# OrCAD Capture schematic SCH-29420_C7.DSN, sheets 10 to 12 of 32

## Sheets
10 P07_POWER SUPPLY: size A2
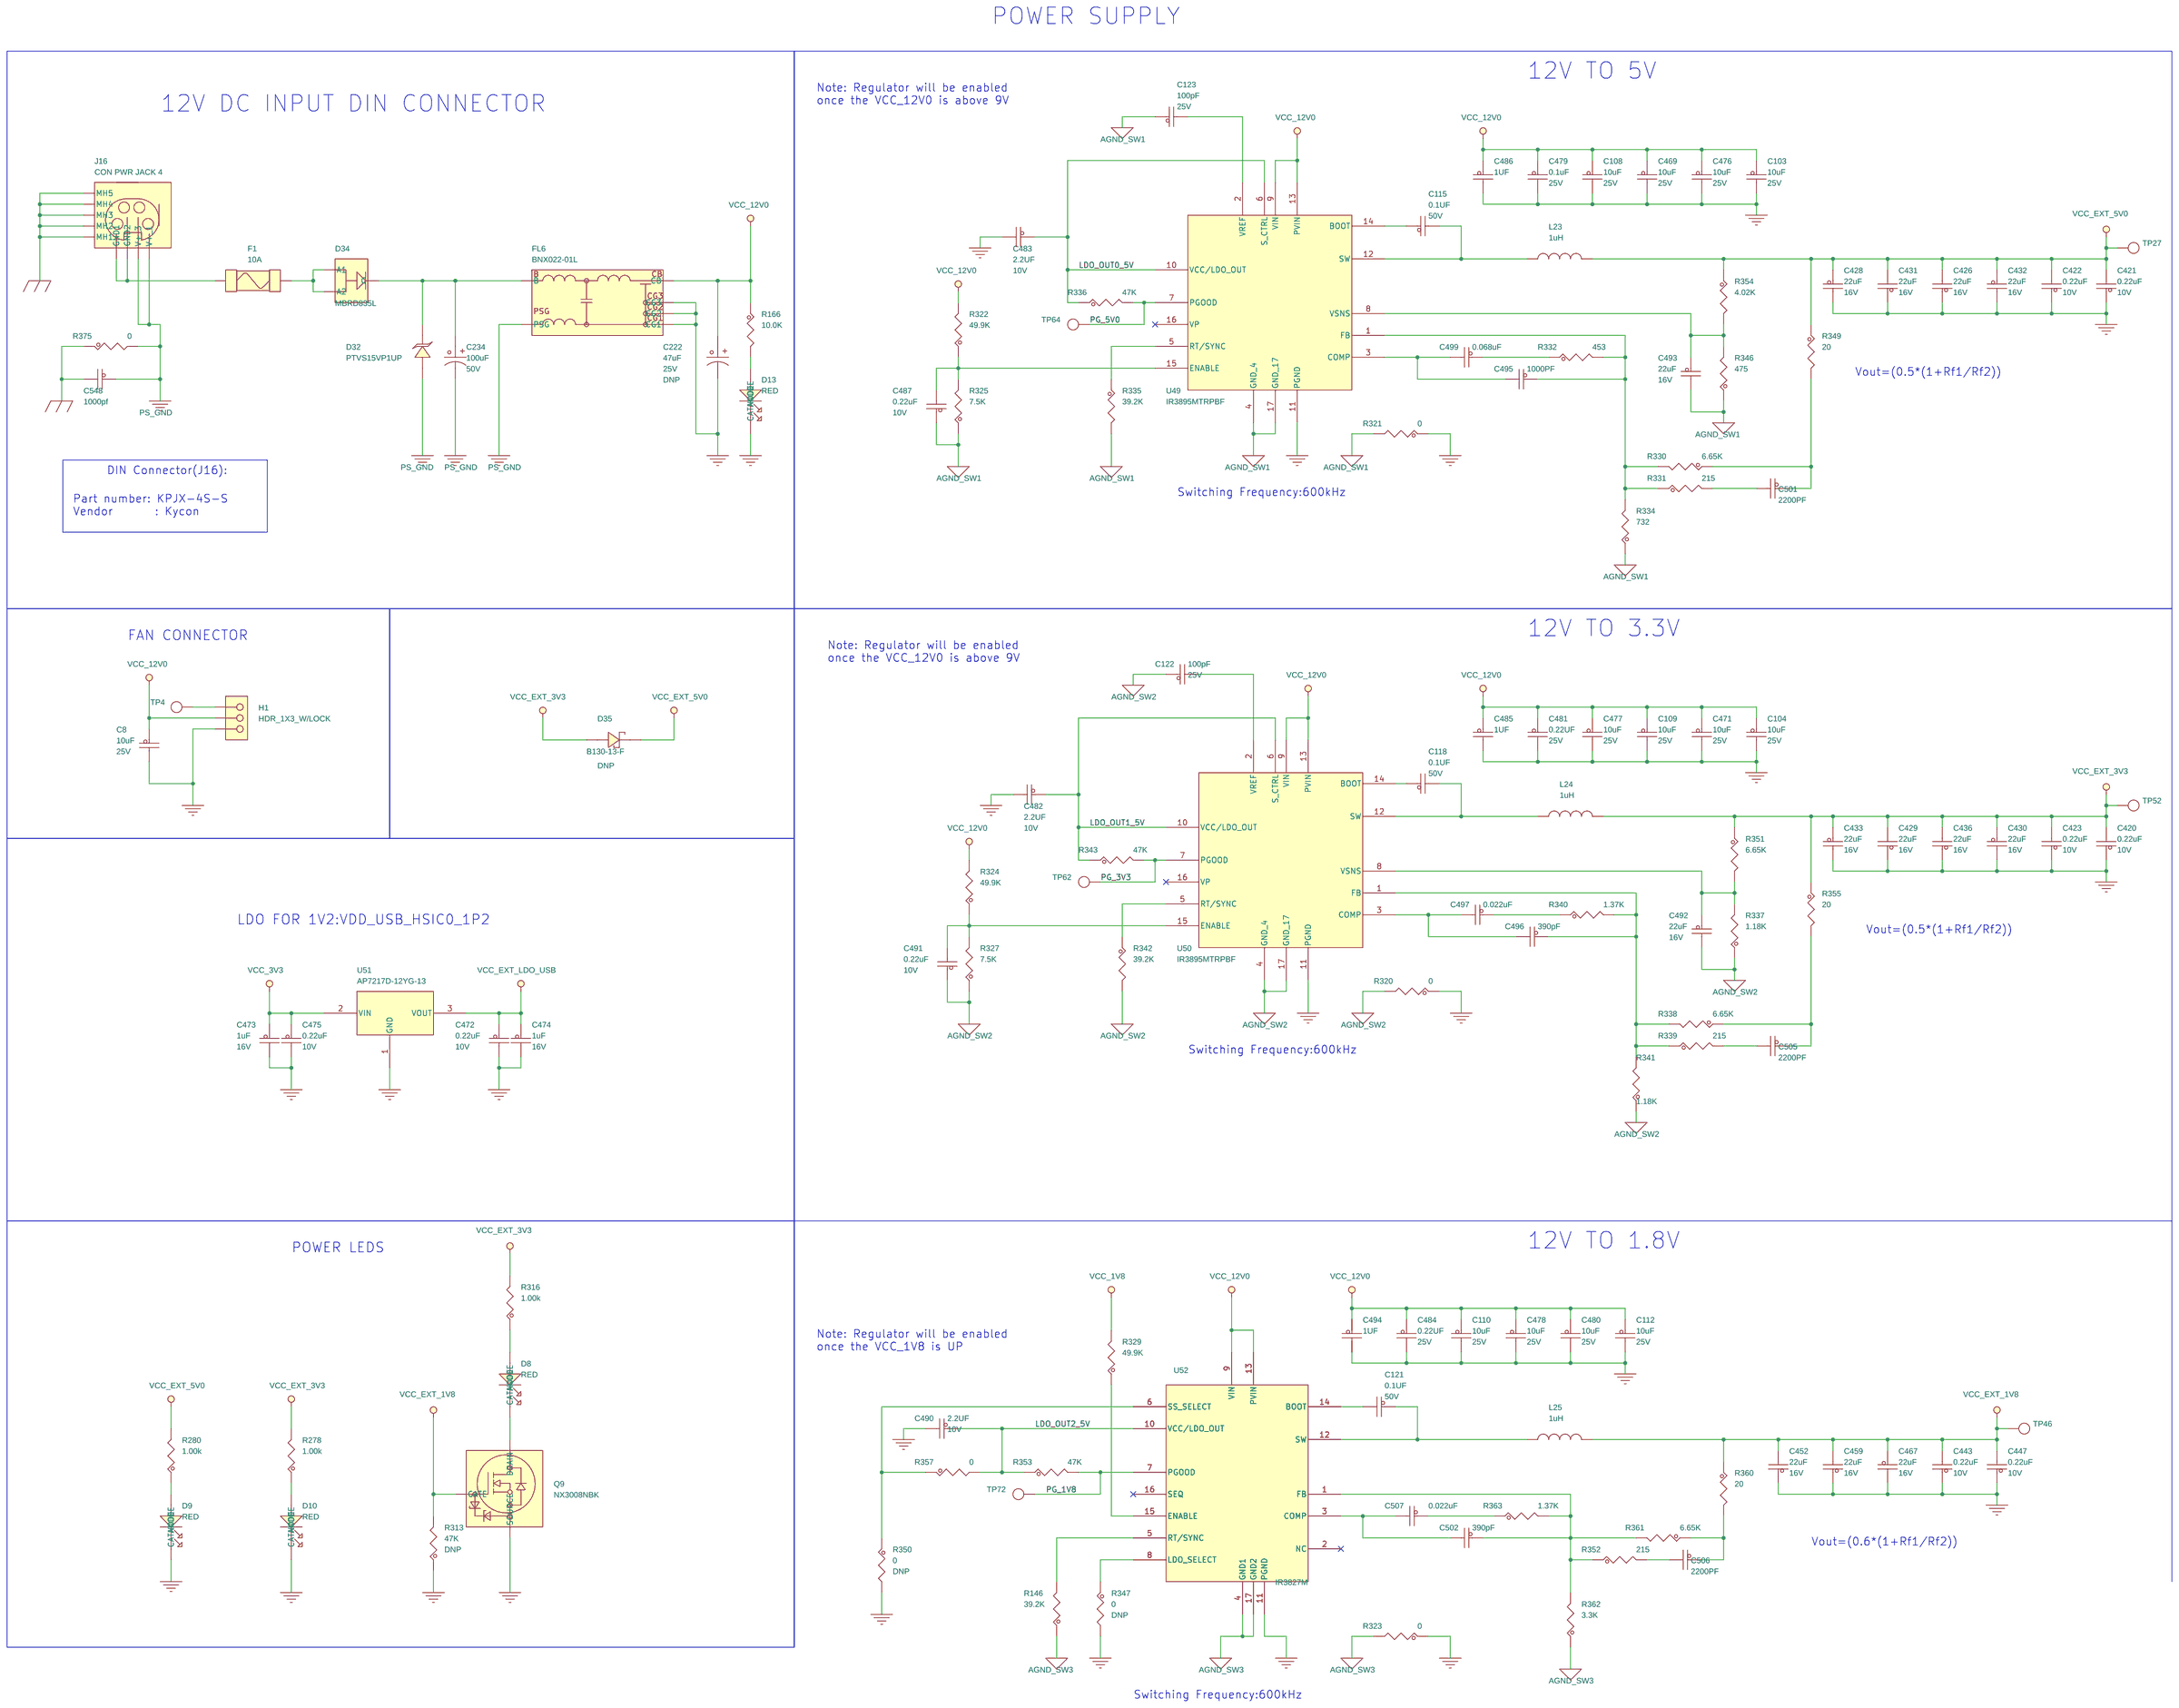
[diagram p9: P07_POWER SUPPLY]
11 P08_PMIC_1: size A2
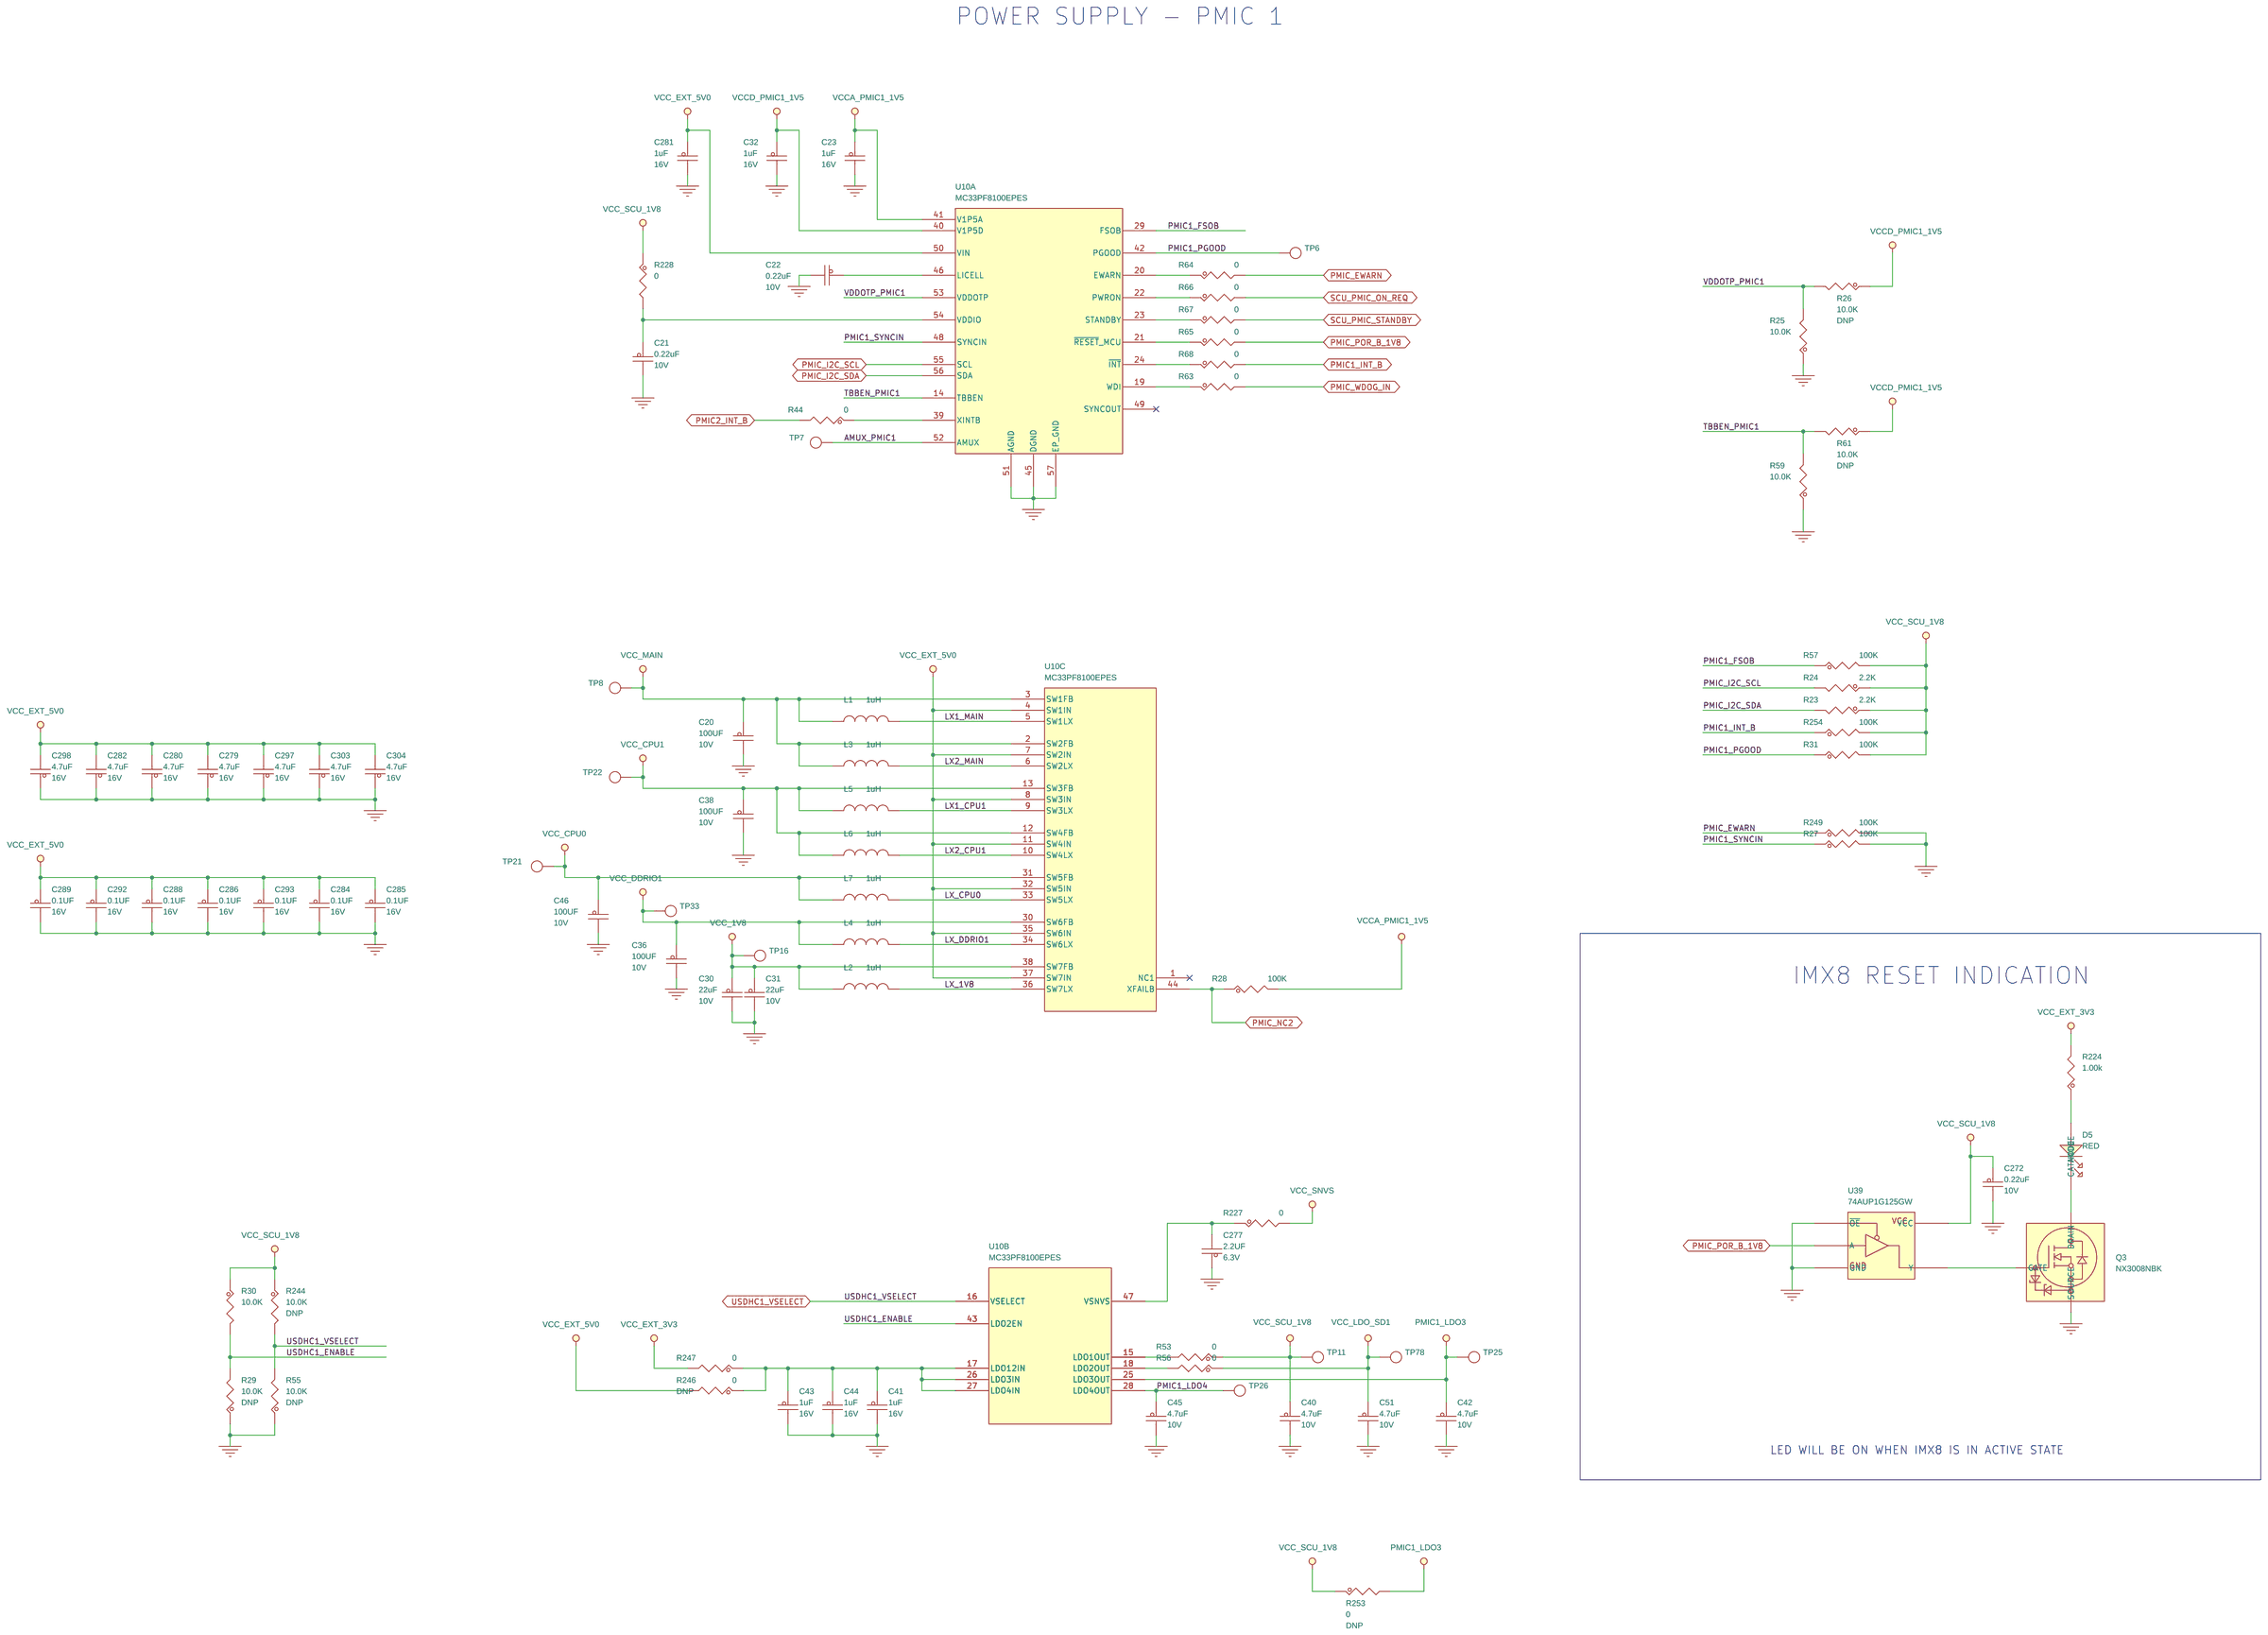
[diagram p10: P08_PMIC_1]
12 P10_MX8QM_POWER: size A2
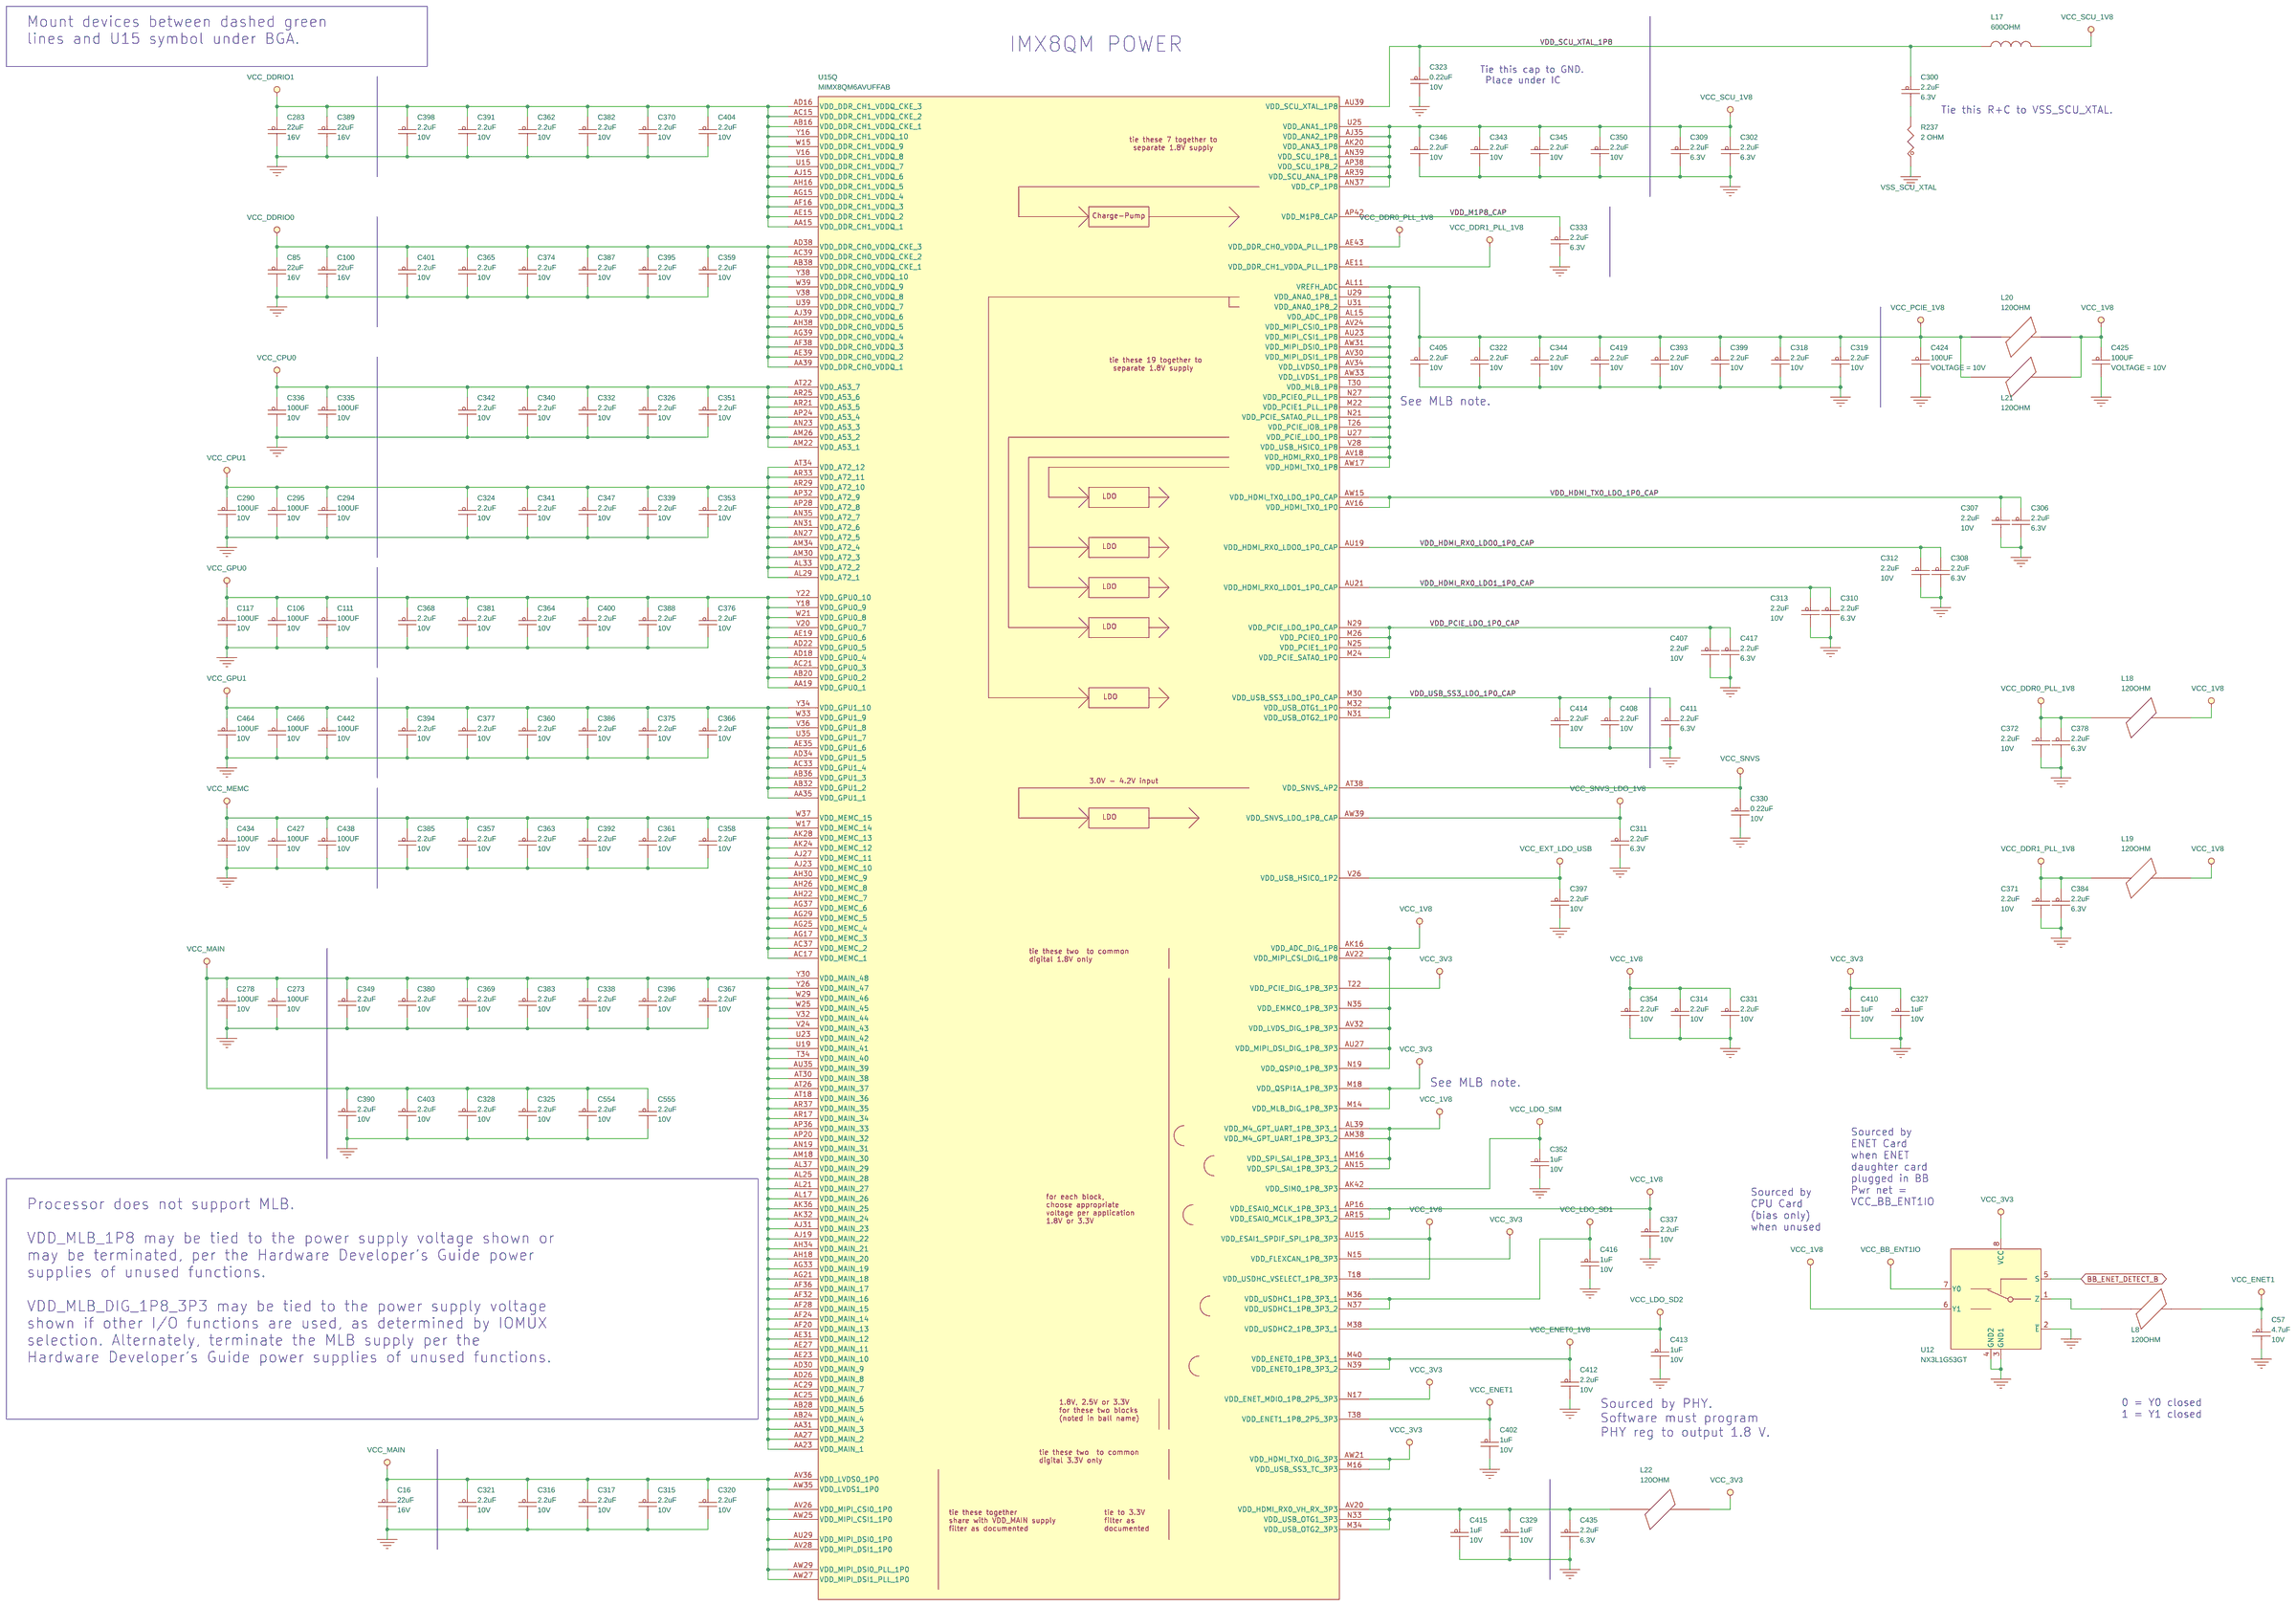
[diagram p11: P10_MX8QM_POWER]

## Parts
sheet P07_POWER SUPPLY
C8  10uF  [CC0603_OV]
C103  10uF  [CC0603_OV]
C104  10uF  [CC0603_OV]
C108  10uF  [CC0603_OV]
C109  10uF  [CC0603_OV]
C110  10uF  [CC0603_OV]
C112  10uF  [CC0603_OV]
C115  0.1UF  [CC0402_25]
C118  0.1UF  [CC0402_25]
C121  0.1UF  [CC0402_25]
C122  100pF  [CC0402_25]
C123  100pF  [CC0402_25]
C222  47uF  [cce6p8x6p8]
C234  100uF  [cce6p8x6p8]
C420  0.22uF  [CC0402_25]
C421  0.22uF  [CC0402_25]
C422  0.22uF  [CC0402_25]
C423  0.22uF  [CC0402_25]
C426  22uF  [CC0805_OV]
C428  22uF  [CC0805_OV]
C429  22uF  [CC0805_OV]
C430  22uF  [CC0805_OV]
C431  22uF  [CC0805_OV]
C432  22uF  [CC0805_OV]
C433  22uF  [CC0805_OV]
C436  22uF  [CC0805_OV]
C443  0.22uF  [CC0402_25]
C447  0.22uF  [CC0402_25]
C452  22uF  [CC0805_OV]
C459  22uF  [CC0805_OV]
C467  22uF  [CC0805_OV]
C469  10uF  [CC0603_OV]
C471  10uF  [CC0603_OV]
C472  0.22uF  [CC0402_25]
C473  1uF  [CC0402_25]
C474  1uF  [CC0402_25]
C475  0.22uF  [CC0402_25]
C476  10uF  [CC0603_OV]
C477  10uF  [CC0603_OV]
C478  10uF  [CC0603_OV]
C479  0.1uF  [CC0402_25]
C480  10uF  [CC0603_OV]
C481  0.22UF  [CC0805_OV]
C482  2.2UF  [CC0402_25]
C483  2.2UF  [CC0402_25]
C484  0.22UF  [CC0805_OV]
C485  1UF  [CC0603_OV]
C486  1UF  [CC0603_OV]
C487  0.22uF  [CC0402_25]
C490  2.2UF  [CC0402_25]
C491  0.22uF  [CC0402_25]
C492  22uF  [CC0805_OV]
C493  22uF  [CC0805_OV]
C494  1UF  [CC0603_OV]
C495  1000PF  [CC0402_25]
C496  390pF  [CC0402_25]
C497  0.022uF  [CC0402_25]
C499  0.068uF  [CC0603_OV]
C501  2200PF  [CC0402_25]
C502  390pF  [CC0402_25]
C505  2200PF  [CC0402_25]
C506  2200PF  [CC0402_25]
C507  0.022uF  [CC0402_25]
C548  1000pf  [CC1210]
D8  RED  [LED_0603]
D9  RED  [LED_0603]
D10  RED  [LED_0603]
D13  RED  [LED_0603]
D32  PTVS15VP1UP  [sod-128]
D34  MBRD835L  [DPAK]
D35  B130-13-F  [sma2_4_4p6x2p9]
F1  10A  [FUSE_BLOCK_154]
FL6  BNX022-01L  [filter6_12p3x9p3]
H1  HDR_1X3_W/LOCK  [hdr1x3_100_294x250_th]
J16  CON PWR JACK 4  [jack_pwr_ra_4p]
L23  1uH  [ind2_10p7x10p7]
L24  1uH  [ind2_10p7x10p7]
L25  1uH  [ind2_4p3sq_xfl4020]
Q9  NX3008NBK  [SOT23_A]
R146  39.2K  [RC0402_25]
R166  10.0K  [RC0402_25]
R278  1.00k  [RC0402_25]
R280  1.00k  [RC0402_25]
R313  47K  [RC0402_25]
R316  1.00k  [RC0402_25]
R320  0  [RC0402_25]
R321  0  [RC0402_25]
R322  49.9K  [RC0402_25]
R323  0  [RC0402_25]
R324  49.9K  [RC0402_25]
R325  7.5K  [RC0402_25]
R327  7.5K  [RC0402_25]
R329  49.9K  [RC0402_25]
R330  6.65K  [RC0402_25]
R331  215  [RC0402_25]
R332  453  [RC0402_25]
R334  732  [RC0402_25]
R335  39.2K  [RC0402_25]
R336  47K  [RC0402_25]
R337  1.18K  [RC0402_25]
R338  6.65K  [RC0402_25]
R339  215  [RC0402_25]
R340  1.37K  [RC0402_25]
R341  1.18K  [RC0402_25]
R342  39.2K  [RC0402_25]
R343  47K  [RC0402_25]
R346  475  [RC0402_25]
R347  0  [RC0402_25]
R349  20  [RC0402_25]
R350  0  [RC0402_25]
R351  6.65K  [RC0402_25]
R352  215  [RC0402_25]
R353  47K  [RC0402_25]
R354  4.02K  [RC0402_25]
R355  20  [RC0402_25]
R357  0  [RC0402_25]
R360  20  [RC0402_25]
R361  6.65K  [RC0402_25]
R362  3.3K  [RC0402_25]
R363  1.37K  [RC0402_25]
R375  0  [RC0402_25]
TP4  TPAD_050  [TPAD_050]
TP27  TPAD_050  [TPAD_050]
TP46  TPAD_050  [TPAD_050]
TP52  TPAD_050  [TPAD_050]
TP62  TPAD_050  [TPAD_050]
TP64  TPAD_050  [TPAD_050]
TP72  TPAD_050  [TPAD_050]
U49  IR3895MTRPBF  [qfn17_0p65_5x6]
U50  IR3895MTRPBF  [qfn17_0p65_5x6]
U51  AP7217D-12YG-13  [sot89_123]
U52  IR3827M  [QFN17_0P5_4X5]
sheet P08_PMIC_1
C20  100UF  [CC1210]
C21  0.22uF  [CC0402_25]
C22  0.22uF  [CC0402_25]
C23  1uF  [CC0402_25]
C30  22uF  [CC0603_OV]
C31  22uF  [CC0603_OV]
C32  1uF  [CC0402_25]
C36  100UF  [CC1210]
C38  100UF  [CC1210]
C40  4.7uF  [CC0402_25]
C41  1uF  [CC0402_25]
C42  4.7uF  [CC0402_25]
C43  1uF  [CC0402_25]
C44  1uF  [CC0402_25]
C45  4.7uF  [CC0402_25]
C46  100UF  [CC1210]
C51  4.7uF  [CC0402_25]
C272  0.22uF  [CC0402_25]
C277  2.2UF  [CC0402_25]
C279  4.7uF  [CC0603_OV]
C280  4.7uF  [CC0603_OV]
C281  1uF  [CC0402_25]
C282  4.7uF  [CC0603_OV]
C284  0.1UF  [CC0402_25]
C285  0.1UF  [CC0402_25]
C286  0.1UF  [CC0402_25]
C288  0.1UF  [CC0402_25]
C289  0.1UF  [CC0402_25]
C292  0.1UF  [CC0402_25]
C293  0.1UF  [CC0402_25]
C297  4.7uF  [CC0603_OV]
C298  4.7uF  [CC0603_OV]
C303  4.7uF  [CC0603_OV]
C304  4.7uF  [CC0603_OV]
D5  RED  [LED_0603]
L1  1uH  [ind2520]
L2  1uH  [ind2520]
L3  1uH  [ind2520]
L4  1uH  [ind2520]
L5  1uH  [ind2520]
L6  1uH  [ind2520]
L7  1uH  [ind2520]
Q3  NX3008NBK  [SOT23_A]
R23  2.2K  [RC0402_25]
R24  2.2K  [RC0402_25]
R25  10.0K  [RC0402_25]
R26  10.0K  [RC0402_25]
R27  100K  [RC0402_25]
R28  100K  [RC0402_25]
R29  10.0K  [RC0402_25]
R30  10.0K  [RC0402_25]
R31  100K  [RC0402_25]
R44  0  [RC0402_25]
R53  0  [RC0402_25]
R55  10.0K  [RC0402_25]
R56  0  [RC0402_25]
R57  100K  [RC0402_25]
R59  10.0K  [RC0402_25]
R61  10.0K  [RC0402_25]
R63  0  [RC0402_25]
R64  0  [RC0402_25]
R65  0  [RC0402_25]
R66  0  [RC0402_25]
R67  0  [RC0402_25]
R68  0  [RC0402_25]
R224  1.00k  [RC0402_25]
R227  0  [RC0402_25]
R228  0  [RC0402_25]
R244  10.0K  [RC0402_25]
R246  0  [RC0402_25]
R247  0  [RC0402_25]
R249  100K  [RC0402_25]
R253  0  [RC0402_25]
R254  100K  [RC0402_25]
TP6  TPAD_050  [TPAD_050]
TP7  TPAD_050  [TPAD_050]
TP8  TPAD_050  [TPAD_050]
TP11  TPAD_050  [TPAD_050]
TP16  TPAD_050  [TPAD_050]
TP21  TPAD_050  [TPAD_050]
TP22  TPAD_050  [TPAD_050]
TP25  TPAD_050  [TPAD_050]
TP26  TPAD_050  [TPAD_050]
TP33  TPAD_050  [TPAD_050]
TP78  TPAD_050  [TPAD_050]
U10  MC33PF8100EPES  [qfn56_0p5_8x8_ep217x199]  (sections A,B,C)
U39  74AUP1G125GW  [SC70-5]
sheet P10_MX8QM_POWER
C16  22uF  [CC1210]
C57  4.7uF  [CC0603_OV]
C85  22uF  [CC1210]
C100  22uF  [CC1210]
C106  100UF  [CC1210]
C111  100UF  [CC1210]
C117  100UF  [CC1210]
C273  100UF  [CC1210]
C278  100UF  [CC1210]
C283  22uF  [CC1210]
C290  100UF  [CC1210]
C294  100UF  [CC1210]
C295  100UF  [CC1210]
C300  2.2uF  [CC0603_OV]
C302  2.2uF  [CC0603_OV]
C306  2.2uF  [CC0603_OV]
C307  2.2uF  [CC0402_25]
C308  2.2uF  [CC0603_OV]
C309  2.2uF  [CC0603_OV]
C310  2.2uF  [CC0603_OV]
C311  2.2uF  [CC0603_OV]
C312  2.2uF  [CC0402_25]
C313  2.2uF  [CC0402_25]
C314  2.2uF  [CC0402_25]
C315  2.2uF  [CC0402_25]
C316  2.2uF  [CC0402_25]
C317  2.2uF  [CC0402_25]
C318  2.2uF  [CC0402_25]
C319  2.2uF  [CC0402_25]
C320  2.2uF  [CC0402_25]
C321  2.2uF  [CC0402_25]
C322  2.2uF  [CC0402_25]
C323  0.22uF  [CC0402_25]
C324  2.2uF  [0402_CC]
C325  2.2uF  [0402_CC]
C326  2.2uF  [CC0402_25]
C327  1uF  [0402_CC]
C328  2.2uF  [0402_CC]
C329  1uF  [0402_CC]
C330  0.22uF  [CC0402_25]
C331  2.2uF  [0402_CC]
C332  2.2uF  [0402_CC]
C333  2.2uF  [CC0603_OV]
C335  100UF  [CC1210]
C336  100UF  [CC1210]
C337  2.2uF  [CC0402_25]
C338  2.2uF  [0402_CC]
C339  2.2uF  [0402_CC]
C340  2.2uF  [0402_CC]
C341  2.2uF  [0402_CC]
C342  2.2uF  [0402_CC]
C343  2.2uF  [0402_CC]
C344  2.2uF  [CC0402_25]
C345  2.2uF  [0402_CC]
C346  2.2uF  [0402_CC]
C347  2.2uF  [0402_CC]
C349  2.2uF  [0402_CC]
C350  2.2uF  [0402_CC]
C351  2.2uF  [0402_CC]
C352  1uF  [0402_CC]
C353  2.2uF  [0402_CC]
C354  2.2uF  [CC0402_25]
C357  2.2uF  [0402_CC]
C358  2.2uF  [0402_CC]
C359  2.2uF  [CC0402_25]
C360  2.2uF  [0402_CC]
C361  2.2uF  [0402_CC]
C362  2.2uF  [CC0402_25]
C363  2.2uF  [0402_CC]
C364  2.2uF  [0402_CC]
C365  2.2uF  [CC0402_25]
C366  2.2uF  [0402_CC]
C367  2.2uF  [0402_CC]
C368  2.2uF  [0402_CC]
C369  2.2uF  [0402_CC]
C370  2.2uF  [CC0402_25]
C371  2.2uF  [CC0402_25]
C372  2.2uF  [CC0402_25]
C374  2.2uF  [CC0402_25]
C375  2.2uF  [0402_CC]
C376  2.2uF  [0402_CC]
C377  2.2uF  [0402_CC]
C378  2.2uF  [CC0603_OV]
C380  2.2uF  [0402_CC]
C381  2.2uF  [0402_CC]
C382  2.2uF  [CC0402_25]
C383  2.2uF  [0402_CC]
C384  2.2uF  [CC0603_OV]
C385  2.2uF  [0402_CC]
C386  2.2uF  [0402_CC]
C387  2.2uF  [CC0402_25]
C388  2.2uF  [0402_CC]
C389  22uF  [CC1210]
C390  2.2uF  [0402_CC]
C391  2.2uF  [CC0402_25]
C392  2.2uF  [0402_CC]
C393  2.2uF  [0402_CC]
C394  2.2uF  [0402_CC]
C395  2.2uF  [CC0402_25]
C396  2.2uF  [0402_CC]
C397  2.2uF  [0402_CC]
C398  2.2uF  [CC0402_25]
C399  2.2uF  [0402_CC]
C400  2.2uF  [0402_CC]
C401  2.2uF  [CC0402_25]
C402  1uF  [0402_CC]
C403  2.2uF  [0402_CC]
C404  2.2uF  [CC0402_25]
C405  2.2uF  [0402_CC]
C407  2.2uF  [0402_CC]
C408  2.2uF  [0402_CC]
C410  1uF  [CC0402_25]
C411  2.2uF  [CC0603_OV]
C412  2.2uF  [CC0402_25]
C413  1uF  [CC0402_25]
C414  2.2uF  [CC0402_25]
C415  1uF  [CC0402_25]
C416  1uF  [CC0402_25]
C417  2.2uF  [CC0603_OV]
C419  2.2uF  [CC0402_25]
C424  100UF  [CC1210]
C425  100UF  [CC1210]
C427  100UF  [CC1210]
C434  100UF  [CC1210]
C435  2.2uF  [CC0603_OV]
C438  100UF  [CC1210]
C442  100UF  [CC1210]
C464  100UF  [CC1210]
C466  100UF  [CC1210]
C554  2.2uF  [0402_CC]
C555  2.2uF  [0402_CC]
L8  120OHM  [IND_0603]
L17  600OHM  [ind_1p8x1mm_sm]
L18  120OHM  [IND_0603]
L19  120OHM  [IND_0603]
L20  120OHM  [IND_0603]
L21  120OHM  [IND_0603]
L22  120OHM  [IND_0603]
R237  2 OHM  [RC0402_25]
U12  NX3L1G53GT  [xson_8p]
sheet P20_USB3.x_TYPE_C
U15  MIMX8QM6AVUFFAB  [imx8_bga_1313]  (sections A,B,C,D,E,F,G,H,I,J,K,L,M,N,O,P,Q,R,S,T,U)

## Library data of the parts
C8 C103 C104 C108-C110 C112 C469 C471 C476-C478 C480 = CAP_NP: CAP CER 10uF 25V 20% X5R 0603; AGILE_PN: 150-79272; CAD_APPROVED: Yes; EN: 102-1-01982; FPLIST: CC0603_OV,CC0603,0603_CC; HEIGHT: 1MM; MFG_NAME01: Murata; MFG_PN01: GRM188R61E106MA73D; ROHS: Yes; TOL: 20%; Tolerance: 20%; VOLTAGE: 25V
C115 C118 C121 = CAP_NP: CAP CER 0.1UF 50V 10% X5R 0402; AGILE_PN: 150-79249; CAD_APPROVED: Yes; EN: 102-1-01811; FPLIST: CC0402_25,CC0402_HD,0402_CC; HEIGHT: 0.55MM; MFG_NAME01: MURATA; MFG_PN01: GRM155R61H104KE19; ROHS: Yes; TOL: 10%; Tolerance: 10%; VOLTAGE: 50V
C122 C123 = CAP_NP: CAP CER 100pF 25V 10% X7R 0402; AGILE_PN: 150-30222; CAD_APPROVED: Yes; EN: 102-1-00028; FPLIST: CC0402_25,CC0402_HD,0402_CC; HEIGHT: 0.55MM; MFG_NAME01: YAGEO AMERICA; MFG_PN01: CC0402KRX7R8BB101; ROHS: Yes; TOL: 10%; Tolerance: 10%; VOLTAGE: 25V
C222 = CAP_POL: CAP ALEL 47uF 35V 20% -- AEC-Q200 SMT; AGILE_PN: 150-79508; ASSY_OPT: DNP; CAD_APPROVED: Yes; EN: 102-3-00024; HEIGHT: 5.5 MM; MFG_NAME01: Panasonic; MFG_PN01: EEE1VA470WAP; ROHS: Yes; VOLTAGE: 25V
C234 = CAP_POL: CAP ALEL 100uF 50V 20% -- AEC-Q200 SMT; AGILE_PN: 150-80098; CAD_APPROVED: Yes; EN: 102-3-00161; HEIGHT: 8 MM; MFG_NAME01: PANASONIC; MFG_PN01: EEE-FTH101XAP; ROHS: Yes; TOL: 20%; Temp_Range: -55°C to +105°C; Tolerance: 20%; VOLTAGE: 50V
C21 C22 C272 C323 C330 C420-C423 C443 C447 C472 C475 C487 C491 = CAP_NP: CAP CER 0.22uF 10V 10% X7R AEC-Q200 0402; AGILE_PN: 150-79031; CAD_APPROVED: Yes; EN: 102-1-01816; FPLIST: CC0402_25,CC0402_HD,0402_CC; HEIGHT: 0.55MM; MFG_NAME01: TDK; MFG_PN01: CGA2B1X7R1A224K050BC; ROHS: Yes; TOL: 10%; Tolerance: 10%; VOLTAGE: 10V
C426 C428-C433 C436 C452 C459 C467 C492 C493 = CAP_NP: CAP CER 22UF 16V 10% X5R 0805; AGILE_PN: 150-78843; CAD_APPROVED: Yes; EN: 102-1-01914; FPLIST: CC0805_OV,CC0805,0805_CC; HEIGHT: 1.45MM; MFG_NAME01: TDK; MFG_PN01: C2012X5R1C226K; ROHS: Yes; TOL: 10%; Tolerance: 10%; VOLTAGE: 16V
C23 C32 C41 C43 C44 C281 C473 C474 = CAP_NP: CAP CER 1uF 16V 10% X5R 0402; AGILE_PN: 150-79794; CAD_APPROVED: Yes; EN: 102-1-01641; FPLIST: CC0402_25,CC0402_HD,0402_CC; HEIGHT: 0.55MM; MFG_NAME01: NIC COMPONENTS CORP; MFG_PN01: NMC0402X5R105K16TRPF; ROHS: Yes; TOL: +/-10%; Tolerance: +/-10%; VOLTAGE: 16V
C479 = CAP_NP: CAP CER 0.1UF 25V 10% X5R 0402; AGILE_PN: 150-78633; CAD_APPROVED: Yes; EN: 102-1-01693; FPLIST: CC0402_25,CC0402_HD,0402_CC; HEIGHT: 0.55MM; MFG_NAME01: YAGEO AMERICA; MFG_PN01: CC0402KRX5R8BB104; ROHS: Yes; TOL: 10%; Tolerance: 10%; VOLTAGE: 25V
C481 C484 = CAP_NP: CAP CER 0.22UF 25V 10% X7R 0805; AGILE_PN: 150-75497; CAD_APPROVED: Yes; EN: 102-1-00372; FPLIST: CC0805_OV,CC0805,0805_CC; HEIGHT: 1.4732MM; MFG_NAME01: AVX; MFG_PN01: 08053C224KAT2A; ROHS: Yes; TOL: 10%; Tolerance: 10%; VOLTAGE: 25V
C482 C483 C490 = CAP_NP: CAP CER 2.2UF 10V 10% X5R 0402; AGILE_PN: 150-79475; CAD_APPROVED: Yes; EN: 102-1-00208; FPLIST: CC0402_25,CC0402_HD,0402_CC; HEIGHT: 0.56MM; MFG_NAME01: AVX; MFG_PN01: 0402ZD225KAT2A; ROHS: Yes; TOL: 10%; Tolerance: 10%; VOLTAGE: 10V
C485 C486 C494 = CAP_NP: CAP CER 1.0UF 25V 10% X5R 0603; AGILE_PN: 150-78563; CAD_APPROVED: Yes; EN: 102-1-01668; FPLIST: CC0603_OV,CC0603,0603_CC; HEIGHT: 0.95MM; MFG_NAME01: AVX; MFG_PN01: 06033D105KAT2A; ROHS: Yes
C495 = CAP_NP: CAP CER 1000PF 50V 10% X7R 0402; AGILE_PN: 150-75271; CAD_APPROVED: Yes; EN: 102-1-00011; FPLIST: CC0402_25,CC0402_HD,0402_CC; HEIGHT: 0.635 MM; MFG_NAME01: AVX; MFG_PN01: 04025C102KAT2A; ROHS: Yes; TOL: +10%; Tolerance: +10%; VOLTAGE: 50VDC
C496 C502 = CAP_NP: CAP CER 390PF 10V 10% X7R 0402; AGILE_PN: 150-80103; CAD_APPROVED: Yes; EN: 102-1-00020; FPLIST: CC0402_25,CC0402_HD,0402_CC; HEIGHT: 0.56MM; MFG_NAME01: AVX; MFG_PN01: 0402ZC391KAT2A; ROHS: Yes; TOL: 10%; Temp_Range: -55°C ~ 125°C; Tolerance: 10%; VOLTAGE: 10V
C497 C507 = CAP_NP: CAP CER 0.022uF 10V 10% X7R 0402; AGILE_PN: 150-80102; CAD_APPROVED: Yes; EN: 102-1-00005; FPLIST: CC0402_25,CC0402_HD,0402_CC; HEIGHT: 0.56MM; MFG_NAME01: AVX; MFG_PN01: 0402ZC223KAT2A; ROHS: Yes; TOL: 10%; Temp_Range: -55°C ~ 125°C; Tolerance: 10%; VOLTAGE: 10V
C499 = CAP_NP: CAP CER 0.068uF 10V 10% X7R 0603; AGILE_PN: 150-80105; CAD_APPROVED: Yes; EN: 102-1-00089; FPLIST: CC0603_OV,CC0603,0603_CC; HEIGHT: 0.9MM; MFG_NAME01: AVX; MFG_PN01: 0603ZC683KAT2A; ROHS: Yes; TOL: 10%; Temp_Range: -55°C ~ 125°C; Tolerance: 10%; VOLTAGE: 10V
C501 C505 C506 = CAP_NP: CAP CER 2200PF 50V 10%  X7R 0402; AGILE_PN: 150-75600; CAD_APPROVED: Yes; EN: 102-1-00062; FPLIST: CC0402_25,CC0402_HD,0402_CC; HEIGHT: 0.55MM; MFG_NAME01: AVX; MFG_PN01: 04025C222KAT2A; ROHS: Yes; TOL: 10%; Tolerance: 10%; VOLTAGE: 50V
C548 = CAP_NP: CAP CER 1000PF 2KV 10% X7R 1210; AGILE_PN: 150-75027; CAD_APPROVED: Yes; EN: 102-1-01612; FPLIST: CC1210,1210_CC; HEIGHT: 1.7MM; MFG_NAME01: AVX; MFG_PN01: 1210GC102KAT1A; ROHS: Yes; TOL: 10%; Tolerance: 10%; VOLTAGE: 2KV
D5 D8-D10 D13 = LED: LED RED SGL 20MA 0603; AGILE_PN: 370-76632; CAD_APPROVED: Yes; EN: 106-4-00247; HEIGHT: 0.45MM; MFG_NAME01: LITE ON; MFG_PN01: LTST-C193KRKT-5A; ROHS: Yes
D32 = DIODE_TVS: DIODE TVS 15V 600W AEC-Q101 SOD-128; AGILE_PN: 480-79835; CAD_APPROVED: Yes; EN: 305-1-00318; HEIGHT: 1.1MM; MFG_NAME01: NEXPERIA; MFG_PN01: PTVS15VP1UP,115; ROHS: Yes
D34 = MBRD835LG: DIODE PWR RECT 8A 35V DPAK; AGILE_PN: 480-30009; CAD_APPROVED: Yes; EN: 106-2-00106; HEIGHT: 2.38mm; MFG_NAME01: ON SEMICONDUCTOR; ROHS: Yes
D35 = DIODE_SCHTKY: DIODE SCH RECT 1A 30V SMA; AGILE_PN: 480-79846; ASSY_OPT: DNP; CAD_APPROVED: Yes; EN: 106-2-00016; HEIGHT: 2.5MM; MFG_NAME01: Diodes Inc; ROHS: Yes; Temp_Range: -65C to 150C
F1 = FUSE: FUSE FAST 10A 125V SMT; AGILE_PN: 510-75758; CAD_APPROVED: Yes; EN: 305-1-00190; HEIGHT: 3.81MM; MFG_NAME01: LITTELFUSE; MFG_PN01: 154010; ROHS: Yes
FL6 = FILTER_BNX028: IC EMI FILTER 20A 50VDC SMT; AGILE_PN: 315-81522; CAD_APPROVED: Yes; EN: 303-0-00065; HEIGHT: 3.3MM; MFG_NAME01: MURATA; ROHS: Yes; Temp_Range: -40&#8451; to 125&#8451;
H1 = CONN_HDR_3X1: HDR 1X3 TH W/LOCK 100MIL SP 435H SN 140L; AGILE_PN: 210-80594; CAD_APPROVED: Yes; EN: 201-1-00649; HEIGHT: 11.05MM; MFG_NAME01: Molex; MFG_PN01: 22-23-2031; ROHS: Yes
J16 = KPJX-4S-S: CON 4 PWR JACK RA SKT SHLD TH -- 591H SN 138L; AGILE_PN: 210-79470; CAD_APPROVED: Yes; EN: 201-2-00073; HEIGHT: 15.25MM; MFG_NAME01: KYCON; ROHS: Yes
L23 L24 = INDUCTOR: IND PWR 1uH@100kHz 16A/20A 20% SMD; AGILE_PN: 180-78692; CAD_APPROVED: Yes; EN: 103-1-00401; HEIGHT: 4.2MM; MFG_NAME01: WURTH ELEKTRONIK EISOS GMBH & CO. KG; MFG_PN01: 7443552100; PART_TYPE: INDUCTOR\POWER; ROHS: Yes; TOL: 20%; Temp_Range: -40C to +155C; Tolerance: 20%
L25 = INDUCTOR: IND PWR 1uH@100KHZ 5.1A 20% AEC-Q200 SMT; AGILE_PN: 180-78198; CAD_APPROVED: Yes; EN: 103-1-00361; HEIGHT: 2.1MM; MFG_NAME01: Coilcraft; MFG_PN01: XFL4020-102ME; ROHS: Yes; TOL: 20%; Tolerance: 20%
Q3 Q9 = NMOS_NX3008NBK: TRAN NMOS PWR 30V 400mA AEC-Q101 SOT23; AGILE_PN: 480-79305; CAD_APPROVED: Yes; EN: 107-2-00226; FPLIST: SOT23_A,TO-236; HEIGHT: 1.1MM; MFG_NAME01: NEXPERIA; MFG_PN01: NX3008NBK,215; ROHS: Yes
R146 R335 R342 = RES: RES MF 39.2K 1/10W 1% AEC-Q200 0402; AGILE_PN: 470-31014; CAD_APPROVED: Yes; EN: 101-1-00446; FPLIST: RC0402_25,RC0402_HD,0402_CC; HEIGHT: 0.40 MM; MFG_NAME01: KOA SPEER; MFG_PN01: RK73H1ETTP3922F; ROHS: Yes; TOL: 1%; Temp_Range: -55C to +155C; Tolerance: 1%
R25 R30 R59 R166 = RES: RES MF 10.0K 1/16W 1% 0402; AGILE_PN: 470-80574; CAD_APPROVED: Yes; EN: 101-1-00389; FPLIST: RC0402_25,RC0402_HD,0402_CC; HEIGHT: 0.4MM; MFG_NAME01: WALSIN TECHNOLOGY CORP.; MFG_PN01: WR04X1002FTL; ROHS: Yes; TOL: 1%; Tolerance: 1%
R224 R278 R280 R316 = RES: RES MF 1.00k Ohm 1/16W 1% AEC-Q200 0402; AGILE_PN: 470-80511; CAD_APPROVED: Yes; EN: 101-1-00293; FPLIST: RC0402_25,RC0402_HD,0402_CC; HEIGHT: 0.4 MM; MFG_NAME01: KOA SPEER; MFG_PN01: RK73H1ETTP1001F; ROHS: Yes; TOL: 1%; Tolerance: 1%
R313 = RES: RES MF 47K 1/10W 1% AEC-Q200 0402; AGILE_PN: 470-81731; ASSY_OPT: DNP; CAD_APPROVED: Yes; EN: 101-1-03402; FPLIST: RC0402_25,RC0402_HD,0402_CC; HEIGHT: 0.40 MM; MFG_NAME01: KOA SPEER; MFG_PN01: RK73H1ETTP4702F; ROHS: Yes; TOL: 1%; Temp_Range: -55C to +155C; Tolerance: 1%
R44 R53 R56 R63-R68 R227 R228 R247 R320 R321 R323 R357 R375 = RES: RES MF ZERO OHM 1/16W -- AEC-Q200 0402; AGILE_PN: 470-80742; CAD_APPROVED: Yes; EN: 101-1-00001; FPLIST: RC0402_25,RC0402_HD,0402_CC; HEIGHT: 0.45 MM; MFG_NAME01: VISHAY INTERTECHNOLOGY; MFG_PN01: CRCW04020000Z0ED; ROHS: Yes
R322 R324 R329 = RES: RES MF 49.9K 1/16W 1% 0402; AGILE_PN: 470-76043; CAD_APPROVED: Yes; EN: 101-1-00456; FPLIST: RC0402_25,RC0402_HD,0402_CC; HEIGHT: 0.4MM; MFG_NAME01: BOURNS; MFG_PN01: CR0402-FX-4992GLF; ROHS: Yes; TOL: 1%; Tolerance: 1%
R325 R327 = RES: RES MF 7.5K 1/10W 1% AEC-Q200 0402; AGILE_PN: 470-81662; CAD_APPROVED: Yes; EN: 101-1-00377; FPLIST: RC0402_25,RC0402_HD,0402_CC; HEIGHT: 0.40 MM; MFG_NAME01: KOA SPEER; MFG_PN01: RK73H1ETTP7501F; ROHS: Yes; TOL: 1%; Temp_Range: -55°C to +155°C; Tolerance: 1%
R330 R338 R351 R361 = RES: RES MF 6.65K 1/16W 1% 0402; AGILE_PN: 470-76485; CAD_APPROVED: Yes; EN: 101-1-00372; FPLIST: RC0402_25,RC0402_HD,0402_CC; HEIGHT: 0.4 MM; MFG_NAME01: VIKING TECH CORPORATION; MFG_PN01: CR-02FL6--6K65; ROHS: Yes; TOL: 1%; Tolerance: 1%
R331 R339 R352 = RES: RES MF 215 OHM 1/10W 1% AEC-Q200 0402; AGILE_PN: 470-30771; CAD_APPROVED: Yes; EN: 101-1-00229; FPLIST: RC0402_25,RC0402_HD,0402_CC; HEIGHT: 0.40 MM; MFG_NAME01: KOA SPEER; MFG_PN01: RK73H1ETTP2150F; ROHS: Yes; TOL: 1%; Temp_Range: -55C to +155C; Tolerance: 1%
R332 = RES: RES MF 453 OHM 1/10W 1% AEC-Q200 0402; AGILE_PN: 470-81549; CAD_APPROVED: Yes; EN: 101-1-00260; FPLIST: RC0402_25,RC0402_HD,0402_CC; HEIGHT: 0.40 MM; MFG_NAME01: KOA SPEER; MFG_PN01: RK73H1ETTP4530F; ROHS: Yes; TOL: 1%; Temp_Range: -55C to +155C; Tolerance: 1%
R334 = RES: RES MF 732 OHM 1/10W 1% AEC-Q200 0402; AGILE_PN: 470-30821; CAD_APPROVED: Yes; EN: 101-1-00280; FPLIST: RC0402_25,RC0402_HD,0402_CC; HEIGHT: 0.40 MM; MFG_NAME01: KOA SPEER; MFG_PN01: RK73H1ETTP7320F; ROHS: Yes; TOL: 1%; Temp_Range: -55C to +155C; Tolerance: 1%
R336 R343 R353 = RES: RES MF 47K 1/10W 1% AEC-Q200 0402; AGILE_PN: 470-81731; CAD_APPROVED: Yes; EN: 101-1-03402; FPLIST: RC0402_25,RC0402_HD,0402_CC; HEIGHT: 0.40 MM; MFG_NAME01: KOA SPEER; MFG_PN01: RK73H1ETTP4702F; ROHS: Yes; TOL: 1%; Temp_Range: -55C to +155C; Tolerance: 1%
R337 R341 = RES: RES MF 1.18K  1/10W 1% AEC-Q200 0402; AGILE_PN: 470-81565; CAD_APPROVED: Yes; EN: 101-1-00300; FPLIST: RC0402_25,RC0402_HD,0402_CC; HEIGHT: 0.40 MM; MFG_NAME01: KOA SPEER; MFG_PN01: RK73H1ETTP1181F; ROHS: Yes; TOL: 1%; Temp_Range: -55C to +155C; Tolerance: 1%
R340 R363 = RES: RES MF 1.37K  1/10W 1% AEC-Q200 0402; AGILE_PN: 470-30849; CAD_APPROVED: Yes; EN: 101-1-00306; FPLIST: RC0402_25,RC0402_HD,0402_CC; HEIGHT: 0.40 MM; MFG_NAME01: KOA SPEER; MFG_PN01: RK73H1ETTP1371F; ROHS: Yes; TOL: 1%; Temp_Range: -55°C to +155°C; Tolerance: 1%
R346 = RES: RES MF 475 OHM 1/16W 1% AEC-Q200 0402; AGILE_PN: 470-80979; CAD_APPROVED: Yes; EN: 101-1-00262; FPLIST: RC0402_25,RC0402_HD,0402_CC; HEIGHT: 0.4MM; MFG_NAME01: KOA SPEER; MFG_PN01: RK73H1ETTP4750F; ROHS: Yes; TOL: 1%; Tolerance: 1%
R246 R253 R347 R350 = RES: RES MF ZERO OHM 1/16W -- AEC-Q200 0402; AGILE_PN: 470-80742; ASSY_OPT: DNP; CAD_APPROVED: Yes; EN: 101-1-00001; FPLIST: RC0402_25,RC0402_HD,0402_CC; HEIGHT: 0.45 MM; MFG_NAME01: VISHAY INTERTECHNOLOGY; MFG_PN01: CRCW04020000Z0ED; ROHS: Yes
R349 R355 R360 = RES: RES MF 20 OHM 1/10W 1% AEC-Q200 0402; AGILE_PN: 470-30671; CAD_APPROVED: Yes; EN: 101-1-00130; FPLIST: RC0402_25,RC0402_HD,0402_CC; HEIGHT: 0.40 MM; MFG_NAME01: KOA SPEER; MFG_PN01: RK73H1ETTP20R0F; ROHS: Yes; TOL: 1%; Temp_Range: -55C to +155C; Tolerance: 1%
R354 = RES: RES MF 4.02K 1/10W 1% AEC-Q200 0402; AGILE_PN: 470-81613; CAD_APPROVED: Yes; EN: 101-1-00351; FPLIST: RC0402_25,RC0402_HD,0402_CC; HEIGHT: 0.40 MM; MFG_NAME01: KOA SPEER; MFG_PN01: RK73H1ETTP4021F; ROHS: Yes; TOL: 1%; Temp_Range: -55°C to +155°C; Tolerance: 1%
R362 = RES: RES MF 3.3K 1/16W 5% AEC-Q200 0402; AGILE_PN: 470-80973; CAD_APPROVED: Yes; EN: 101-1-02781; FPLIST: RC0402_25,RC0402_HD,0402_CC; HEIGHT: 0.40 MM; MFG_NAME01: KOA SPEER; MFG_PN01: RK73B1ETTP332J; ROHS: Yes
TP4 TP6-TP8 TP11 TP16 TP21 TP22 TP25-TP27 TP33 TP46 TP52 TP62 TP64 TP72 TP78 = TESTLOOP: TEST POINT PAD 50MIL DIA SMT, NO PART TO ORDER; AGILE_PN: 211-76644; CAD_APPROVED: Yes; HEIGHT: 0.1MM; MFG_NAME01: NOTACOMPONENT; MFG_PN01: NOTACOMPONENT; ROHS: Yes
U49 U50 = IR3895MTR1PBF_QFN_17P: IC VREG BUCK 0.5-12V 16A 1-21V PQFN17; AGILE_PN: 315-79598; CAD_APPROVED: Yes; EN: 301-4-00290; HEIGHT: 1MM; MFG_NAME01: INTERNATIONAL RECTIFIER; ROHS: Yes
U51 = S0T89_3P: IC VREG LDO 1.2V 0.6A 2.5-5.5V SOT89; AGILE_PN: 315-81582; CAD_APPROVED: Yes; EN: 301-4-00257; HEIGHT: 1.6MM; MFG_NAME01: Diodes Inc; ROHS: Yes
U52 = IR3827M_QFN17: IC REG BUCK LDO SYNC 1-21V 6A QFN17; AGILE_PN: 315-81521; CAD_APPROVED: Yes; EN: 301-4-00689; HEIGHT: 1MM; MFG_NAME01: INFINEON TECHNOLOGIES; MFG_PN01: IR3827MTRPBF; ROHS: Yes; Temp_Range: -40C to 125C
C20 C36 C38 C46 C106 C111 C117 C273 C278 C290 C294 C295 C335 C336 C424 C425 C427 C434 C438 C442 C464 C466 = CAP_NP: CAP CER 100UF 10V 10% X7R 1210; AGILE_PN: 150-75975; CAD_APPROVED: Yes; EN: 102-1-02315; FPLIST: CC1210,1210_CC; HEIGHT: 2.413MM; MFG_NAME01: CAPAX TECHNOLOGIES INC.; MFG_PN01: 1210X107K100SNT; ROHS: Yes; TOL: 10%; Tolerance: 10%; VOLTAGE: 10V
C30 C31 = CAP_NP: CAP CER 22uF 10V 20% X5R 0603; AGILE_PN: 150-79530; CAD_APPROVED: Yes; EN: 102-1-01791; FPLIST: CC0603_OV,CC0603,0603_CC; HEIGHT: 1MM; MFG_NAME01: TDK; MFG_PN01: C1608X5R1A226M080AC; ROHS: Yes; TOL: 20%; Tolerance: 20%; VOLTAGE: 10V
C40 C42 C45 C51 = CAP_NP: CAP CER 4.7uF 10V 10% X5R 0402; AGILE_PN: 150-79778; CAD_APPROVED: Yes; EN: 102-1-02063; FPLIST: CC0402_25,CC0402_HD,0402_CC; HEIGHT: 0.65MM; MFG_NAME01: TDK; MFG_PN01: C1005X5R1A475K050BC; ROHS: Yes; TOL: 10%; Tolerance: 10%; VOLTAGE: 10V
C277 = CAP_NP: CAP CER 2.2UF 6.3V 20% X5R 0402; AGILE_PN: 150-76792; CAD_APPROVED: Yes; EN: 102-1-01843; FPLIST: CC0402_25,CC0402_HD,0402_CC; HEIGHT: 0.55MM; MFG_NAME01: KEMET; MFG_PN01: C0402C225M9PACTU; ROHS: Yes; TOL: 20%; Tolerance: 20%; VOLTAGE: 6.3V
C279 C280 C282 C297 C298 C303 C304 = CAP_NP: CAP CER 4.7uF 16V 10% X5R 0603; AGILE_PN: 150-78976; CAD_APPROVED: Yes; EN: 102-1-00091; FPLIST: CC0603_OV,CC0603,0603_CC; HEIGHT: 0.9 MM; MFG_NAME01: TDK; MFG_PN01: C1608X5R1C475K080AC; ROHS: Yes; TOL: 10%; Tolerance: 10%; VOLTAGE: 16V
C284-C286 C288 C289 C292 C293 = CAP_NP: CAP CER 0.1UF 16V 10% X7R 0402; AGILE_PN: 150-75182; CAD_APPROVED: Yes; EN: 102-1-01629; FPLIST: CC0402_25,CC0402_HD,0402_CC; HEIGHT: 0.635MM; MFG_NAME01: AVX; MFG_PN01: 0402YC104KAT2A; ROHS: Yes; TOL: 10%; Tolerance: 10%; VOLTAGE: 16V
L1-L7 = INDUCTOR: IND PWR 1.0uH@1MHZ 4.7A 20% AEC-Q200 SMD; AGILE_PN: 180-78525; CAD_APPROVED: Yes; EN: 103-1-00575; HEIGHT: 1.2MM; MFG_NAME01: TDK; MFG_PN01: TFM252012ALMA1R0MTAA; ROHS: Yes; TOL: 20%
R23 R24 = RES: RES MF 2.2K 1/16W 5% 0402; AGILE_PN: 470-75636; CAD_APPROVED: Yes; EN: 101-1-02777; FPLIST: RC0402_25,RC0402_HD,0402_CC; HEIGHT: 0.4 MM; MFG_NAME01: BOURNS; MFG_PN01: CR0402-JW-222GLF; ROHS: Yes; TOL: 5%; Tolerance: 5%
R26 R29 R55 R61 R244 = RES: RES MF 10.0K 1/16W 1% 0402; AGILE_PN: 470-80574; ASSY_OPT: DNP; CAD_APPROVED: Yes; EN: 101-1-00389; FPLIST: RC0402_25,RC0402_HD,0402_CC; HEIGHT: 0.4MM; MFG_NAME01: WALSIN TECHNOLOGY CORP.; MFG_PN01: WR04X1002FTL; ROHS: Yes; TOL: 1%; Tolerance: 1%
R27 R28 R31 R57 R249 R254 = RES: RES MF 100K 1/16W 5% 0402; AGILE_PN: 470-75597; CAD_APPROVED: Yes; EN: 101-1-02817; FPLIST: RC0402_25,RC0402_HD,0402_CC; HEIGHT: 0.40 MM; MFG_NAME01: VENKEL COMPANY; MFG_PN01: CR0402-16W-104JT; ROHS: Yes; TOL: 5%; Tolerance: 5%
U10 = PC33PF8100A0ES_QFN56: IC POWER MANAGEMENT 12-CH I2C 2.7-5.5V AEC-Q100 QFN56; AGILE_PN: 315-82480; CAD_APPROVED: Yes; HEIGHT: 1.0MM; MFG_NAME01: NXP SEMICONDUCTORS; Package Size: 8 mm x 8 mm x 1 mm; ROHS: Yes; Temp Range: -40C to +105C; VOLTAGE: 2.7-5.5V
U39 = 1G125: IC BUFFER/LINE DRIVER 3STATE 0.8-3.6V SC70-5; AGILE_PN: 315-80956; CAD_APPROVED: Yes; EN: 301-0-01520; HEIGHT: 1.1MM; MFG_NAME01: NEXPERIA; MFG_PN01: 74AUP1G125GW,125; ROHS: Yes
C16 C85 C100 C283 C389 = CAP_NP: CAP CER 22uF 16V 20% X7R AEC-Q200 HF 1210; AGILE_PN: 150-79354; CAD_APPROVED: Yes; EN: 102-1-02278; FPLIST: CC1210,1210_CC; HEIGHT: 2.7MM; MFG_NAME01: Taiyo Yuden; MFG_PN01: EMK325B7226MMHT; ROHS: Yes; TOL: 20%; Tolerance: 20%; VOLTAGE: 16V
C57 = CAP_NP: CAP CER 4.7UF 10V 10% X5R 0603; AGILE_PN: 150-77975; CAD_APPROVED: Yes; EN: 102-1-01650; FPLIST: CC0603_OV,CC0603,0603_CC; HEIGHT: 0.9MM; MFG_NAME01: TAIYO YUDEN; MFG_PN01: LMK107BJ475KA-T; ROHS: Yes; TOL: 10%; Tolerance: 10%; VOLTAGE: 10V
C300 C302 C306 C308-C311 C333 C378 C384 C411 C417 C435 = CAP_NP: CAP CER 2.2uF 6.3V 10% X7R AEC-Q200 0603; AGILE_PN: 150-79352; CAD_APPROVED: Yes; EN: 102-1-02279; FPLIST: CC0603_OV,CC0603,0603_CC; HEIGHT: 0.9MM; MFG_NAME01: TDK; MFG_PN01: CGA3E1X7R0J225K080AC; ROHS: Yes; TOL: 10%; Tolerance: 10%; VOLTAGE: 6.3V
C307 C312-C322 C324-C326 C328 C331 C332 C337-C347 C349-C351 C353 C354 C357-C372 C374-C377 C380-C383 C385-C388 C390-C401 C403-C405 C407 C408 C412 C414 C419 C554 C555 = CAP_NP: CAP CER 2.2uF 10V 10% X7S 0402; AGILE_PN: 150-79706; CAD_APPROVED: Yes; EN: 102-1-02330; FPLIST: CC0402_25,CC0402_HD,0402_CC; HEIGHT: 0.65MM; MFG_NAME01: TDK; MFG_PN01: C1005X7S1A225K050BC; ROHS: Yes; TOL: 10%; Tolerance: 10%; VOLTAGE: 10V
C327 C329 C352 C402 C410 C413 C415 C416 = CAP_NP: CAP CER 1uF 10V 10% X7S AEC-Q200 0402; AGILE_PN: 150-79497; CAD_APPROVED: Yes; EN: 102-1-02280; FPLIST: CC0402_25,CC0402_HD,0402_CC; HEIGHT: 0.7MM; MFG_NAME01: murata; MFG_PN01: GCM155C71A105KE38D; ROHS: Yes; TOL: 10%; Tolerance: 10%; VOLTAGE: 10V
L8 L18-L22 = BEAD_FERRITE: IND FER BEAD 120OHM@100MHZ 2A 25% 0603; AGILE_PN: 180-30008; CAD_APPROVED: Yes; EN: 104-1-00022; FPLIST: IND_0603,0603_CC; HEIGHT: 0.95MM; MFG_NAME01: MURATA; MFG_PN01: BLM18PG121SH1; PART_TYPE: FERRITE; ROHS: Yes; TOL: 25%; Tolerance: 25%
L17 = INDUCTOR: IND FER BEAD 600OHM@100MHz 1A 25% 0603; AGILE_PN: 180-78469; CAD_APPROVED: Yes; EN: 104-1-00111; HEIGHT: 1MM; MFG_NAME01: WURTH ELEKTRONIK EISOS GMBH & CO. KG; MFG_PN01: 742792651; PART_TYPE: FERRITE\BEAD; ROHS: Yes; TOL: +/-25%; Tolerance: +/-25%
R237 = RES: RES MF 2 OHM 1/16W 5% AEC-Q200 0402; AGILE_PN: 470-81371; CAD_APPROVED: Yes; EN: 101-1-00034; FPLIST: RC0402_25,RC0402_HD,0402_CC; HEIGHT: 0.4MM; MFG_NAME01: STACKPOLE ELECTRONICS; MFG_PN01: RMCF0402JT2R00; ROHS: Yes; TOL: 5%; Tolerance: 5%
U12 = NX3L1G53GT_8P: IC SPDT ANALOG SW 1.4-4.3V XSON8; AGILE_PN: 315-81076; CAD_APPROVED: Yes; EN: 301-0-01513; HEIGHT: 0.5MM; MFG_NAME01: NXP SEMICONDUCTORS; MFG_PN01: NX3L1G53GT,115; ROHS: Yes
U15 = PIMX8QM6AVUFFAB_BGA1313: IC CPU QUADMAX 2xA72 1.6GHz 4xA53 1.2GHZ M4 264MHZ FCPBGA1313; AGILE_PN: 330-77094; CAD_APPROVED: Yes; HEIGHT: 2.52MM; MFG_NAME01: NXP SEMICONDUCTORS; ROHS: Yes; Temp Range: -40°C to 125°C

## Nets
AGND_SW1: C123.1 C487.1 C493.2 R321.2 R325.1 R334.1 R335.2 R346.1 U49.4(GND) U49.17(GND)
AGND_SW2: C122.1 C491.1 C492.2 R320.2 R327.1 R337.1 R341.1 R342.2 U50.4(GND) U50.17(GND)
AGND_SW3: R146.1 R323.2 R362.1 U52.4(GND1) U52.17(GND2)
GND: C8.2 C16.2 C20.2 C21.2 C22.2 C23.2 C30.2 C31.2 C32.2 C36.2 C38.2 C40.2 C41.2 C42.2 C43.2 C44.2 C45.2 C46.2 C51.2 C57.2 C85.2 C100.2 C103.2 C104.2 C106.2 C108.2 C109.2 C110.2 C111.2 C112.2 C117.2 C222.2 C272.2 C273.2 C277.1 C278.2 C279.1 C280.1 C281.2 C282.1 C283.2 C284.2 C285.2 C286.2 C288.2 C289.2 C290.2 C292.2 C293.2 C294.2 C295.2 C297.1 C298.1 C302.2 C303.1 C304.1 C306.2 C307.2 C308.2 C309.2 C310.2 C311.2 C312.2 C313.2 C314.2 C315.2 C316.2 C317.2 C318.2 C319.2 C320.2 C321.2 C322.2 C323.2 C324.2 C325.2 C326.2 C327.2 C328.2 C329.2 C330.2 C331.2 C332.2 C333.2 C335.2 C336.2 C337.2 C338.2 C339.2 C340.2 C341.2 C342.2 C343.2 C344.2 C345.2 C346.2 C347.2 C349.2 C350.2 C351.2 C352.2 C353.2 C354.2 C357.2 C358.2 C359.2 C360.2 C361.2 C362.2 C363.2 C364.2 C365.2 C366.2 C367.2 C368.2 C369.2 C370.2 C371.2 C372.2 C374.2 C375.2 C376.2 C377.2 C378.2 C380.2 C381.2 C382.2 C383.2 C384.2 C385.2 C386.2 C387.2 C388.2 C389.2 C390.2 C391.2 C392.2 C393.2 C394.2 C395.2 C396.2 C397.2 C398.2 C399.2 C400.2 C401.2 C402.2 C403.2 C404.2 C405.2 C407.2 C408.2 C410.2 C411.2 C412.2 C413.2 C414.2 C415.2 C416.2 C417.2 C419.2 C420.1 C421.1 C422.1 C423.1 C424.2 C425.2 C426.1 C427.2 C428.2 C429.1 C430.2 C431.1 C432.2 C433.2 C434.2 C435.2 C436.1 C438.2 C442.2 C443.1 C447.1 C452.1 C459.1 C464.2 C466.2 C467.2 C469.2 C471.2 C472.2 C473.2 C474.2 C475.2 C476.2 C477.2 C478.2 C479.2 C480.2 C481.2 C482.2 C483.2 C484.2 C485.2 C486.2 C490.2 C494.2 C554.2 C555.2 D9.C(CATHODE) D10.C(CATHODE) D13.C(CATHODE) FL6.4(CG1) FL6.5(CG2) FL6.6(CG3) H1.3 Q3.2(SOURCE) Q9.2(SOURCE) R25.1 R27.2 R29.1 R55.1 R59.1 R249.2 R313.1 R320.1 R321.1 R323.1 R347.2 R350.2 U10.45(DGND) U10.51(AGND) U10.57(EP_GND) U12.2(~{E}) U12.3(GND1) U12.4(GND2) U39.1(~{OE}) U39.3(GND) U49.11(PGND) U50.11(PGND) U51.1(GND) U52.11(PGND) ; also on sheet 2 5 6 13 14 16 17 18 19 20 21 22 23 24 25 26 27 28 29 30 31 32
GND_DIN: C548.2 J16.5(MH1) J16.6(MH2) J16.7(MH3) J16.8(MH4) J16.9(MH5) R375.1
VCC_1V8: C30.1 C31.1 C314.1 C331.1 C337.1 C354.1 C425.1 L2.1 L18.2 L19.2 L20.2 L21.2 R329.2 TP16.1(Pin1) U10.38(SW7FB) U12.6(Y1) U15.AK16(VDD_ADC_DIG_1P8) U15.AL39(VDD_M4_GPT_UART_1P8_3P3_1) U15.AM16(VDD_SPI_SAI_1P8_3P3_1) U15.AM38(VDD_M4_GPT_UART_1P8_3P3_2) U15.AN15(VDD_SPI_SAI_1P8_3P3_2) U15.AP16(VDD_ESAI0_MCLK_1P8_3P3_1) U15.AR15(VDD_ESAI0_MCLK_1P8_3P3_2) U15.AU15(VDD_ESAI1_SPDIF_SPI_1P8_3P3) U15.AU27(VDD_MIPI_DSI_DIG_1P8_3P3) U15.AV22(VDD_MIPI_CSI_DIG_1P8) U15.AV32(VDD_LVDS_DIG_1P8_3P3) U15.N19(VDD_QSPI0_1P8_3P3) U15.N35(VDD_EMMC0_1P8_3P3) U15.T18(VDD_USDHC_VSELECT_1P8_3P3) ; also on sheet 2 6 15 16 17 18 19 21 24 27 28 31
VCC_3V3: C327.1 C410.1 C473.1 C475.1 L22.1 U12.8(VCC) U15.AW21(VDD_HDMI_TX0_DIG_3P3) U15.M14(VDD_MLB_DIG_1P8_3P3) U15.M16(VDD_USB_SS3_TC_3P3) U15.M18(VDD_QSPI1A_1P8_3P3) U15.N15(VDD_FLEXCAN_1P8_3P3) U15.N17(VDD_ENET_MDIO_1P8_2P5_3P3) U15.T22(VDD_PCIE_DIG_1P8_3P3) U51.2(VIN) ; also on sheet 6 18 20 22 23 24 25 27 28 31
VCC_12V0: C8.1 C103.1 C104.1 C108.1 C109.1 C110.1 C112.1 C222.1 C469.1 C471.1 C476.1 C477.1 C478.1 C479.1 C480.1 C481.1 C484.1 C485.1 C486.1 C494.1 FL6.2(CB) H1.2 R166.1 R322.2 R324.2 U49.9(VIN) U49.13(PVIN) U50.9(VIN) U50.13(PVIN) U52.9(VIN) U52.13(PVIN) ; also on sheet 2 5 22 29 30
VCC_BB_ENT1IO: U12.7(Y0) ; also on sheet 2 31
VCC_CPU0: C46.1 C326.1 C332.1 C335.1 C336.1 C340.1 C342.1 C351.1 L7.1 TP21.1(Pin1) U10.31(SW5FB) U15.AM22(VDD_A53_1) U15.AM26(VDD_A53_2) U15.AN23(VDD_A53_3) U15.AP24(VDD_A53_4) U15.AR21(VDD_A53_5) U15.AR25(VDD_A53_6) U15.AT22(VDD_A53_7)
VCC_CPU1: C38.1 C290.1 C294.1 C295.1 C324.1 C339.1 C341.1 C347.1 C353.1 L5.1 L6.1 TP22.1(Pin1) U10.12(SW4FB) U10.13(SW3FB) U15.AL29(VDD_A72_1) U15.AL33(VDD_A72_2) U15.AM30(VDD_A72_3) U15.AM34(VDD_A72_4) U15.AN27(VDD_A72_5) U15.AN31(VDD_A72_6) U15.AN35(VDD_A72_7) U15.AP28(VDD_A72_8) U15.AP32(VDD_A72_9) U15.AR29(VDD_A72_10) U15.AR33(VDD_A72_11) U15.AT34(VDD_A72_12)
VCC_DDR0_PLL_1V8: C372.1 C378.1 L18.1 U15.AE43(VDD_DDR_CH0_VDDA_PLL_1P8)
VCC_DDR1_PLL_1V8: C371.1 C384.1 L19.1 U15.AE11(VDD_DDR_CH1_VDDA_PLL_1P8)
VCC_DDRIO0: C85.1 C100.1 C359.1 C365.1 C374.1 C387.1 C395.1 C401.1 U15.AA39(VDD_DDR_CH0_VDDQ_1) U15.AB38(VDD_DDR_CH0_VDDQ_CKE_1) U15.AC39(VDD_DDR_CH0_VDDQ_CKE_2) U15.AD38(VDD_DDR_CH0_VDDQ_CKE_3) U15.AE39(VDD_DDR_CH0_VDDQ_2) U15.AF38(VDD_DDR_CH0_VDDQ_3) U15.AG39(VDD_DDR_CH0_VDDQ_4) U15.AH38(VDD_DDR_CH0_VDDQ_5) U15.AJ39(VDD_DDR_CH0_VDDQ_6) U15.U39(VDD_DDR_CH0_VDDQ_7) U15.V38(VDD_DDR_CH0_VDDQ_8) U15.W39(VDD_DDR_CH0_VDDQ_9) U15.Y38(VDD_DDR_CH0_VDDQ_10) ; also on sheet 6 16
VCC_DDRIO1: C36.1 C283.1 C362.1 C370.1 C382.1 C389.1 C391.1 C398.1 C404.1 L4.1 TP33.1(Pin1) U10.30(SW6FB) U15.AA15(VDD_DDR_CH1_VDDQ_1) U15.AB16(VDD_DDR_CH1_VDDQ_CKE_1) U15.AC15(VDD_DDR_CH1_VDDQ_CKE_2) U15.AD16(VDD_DDR_CH1_VDDQ_CKE_3) U15.AE15(VDD_DDR_CH1_VDDQ_2) U15.AF16(VDD_DDR_CH1_VDDQ_3) U15.AG15(VDD_DDR_CH1_VDDQ_4) U15.AH16(VDD_DDR_CH1_VDDQ_5) U15.AJ15(VDD_DDR_CH1_VDDQ_6) U15.U15(VDD_DDR_CH1_VDDQ_7) U15.V16(VDD_DDR_CH1_VDDQ_8) U15.W15(VDD_DDR_CH1_VDDQ_9) U15.Y16(VDD_DDR_CH1_VDDQ_10) ; also on sheet 17
VCC_ENET0_1V8: C412.1 U15.M40(VDD_ENET0_1P8_3P3_1) U15.N39(VDD_ENET0_1P8_3P3_2) ; also on sheet 24
VCC_ENET1: C57.1 C402.1 L8.2 U15.T38(VDD_ENET1_1P8_2P5_3P3)
VCC_EXT_1V8: C443.2 C447.2 C452.2 C459.2 C467.1 L25.2 Q9.1(GATE) R313.2 R360.1 TP46.1(Pin1) ; also on sheet 2 5 6 14 29 30
VCC_EXT_3V3: C420.2 C423.2 C429.2 C430.1 C433.1 C436.2 D35.A L24.2 R224.2 R247.2 R278.2 R316.2 R351.1 R355.1 TP52.1(Pin1) ; also on sheet 6 18
VCC_EXT_5V0: C279.2 C280.2 C281.1 C282.2 C284.1 C285.1 C286.1 C288.1 C289.1 C292.1 C293.1 C297.2 C298.2 C303.2 C304.2 C421.2 C422.2 C426.2 C428.1 C431.2 C432.1 D35.C L23.2 R246.2 R280.2 R349.1 R354.1 TP27.1(Pin1) U10.4(SW1IN) U10.7(SW2IN) U10.8(SW3IN) U10.11(SW4IN) U10.32(SW5IN) U10.35(SW6IN) U10.37(SW7IN) U10.50(VIN) ; also on sheet 6
VCC_EXT_LDO_USB: C397.1 C472.1 C474.1 U15.V26(VDD_USB_HSIC0_1P2) U51.3(VOUT)
VCC_GPU0: C106.1 C111.1 C117.1 C364.1 C368.1 C376.1 C381.1 C388.1 C400.1 U15.AA19(VDD_GPU0_1) U15.AB20(VDD_GPU0_2) U15.AC21(VDD_GPU0_3) U15.AD18(VDD_GPU0_4) U15.AD22(VDD_GPU0_5) U15.AE19(VDD_GPU0_6) U15.V20(VDD_GPU0_7) U15.W21(VDD_GPU0_8) U15.Y18(VDD_GPU0_9) U15.Y22(VDD_GPU0_10) ; also on sheet 6
VCC_GPU1: C360.1 C366.1 C375.1 C377.1 C386.1 C394.1 C442.1 C464.1 C466.1 U15.AA35(VDD_GPU1_1) U15.AB32(VDD_GPU1_2) U15.AB36(VDD_GPU1_3) U15.AC33(VDD_GPU1_4) U15.AD34(VDD_GPU1_5) U15.AE35(VDD_GPU1_6) U15.U35(VDD_GPU1_7) U15.V36(VDD_GPU1_8) U15.W33(VDD_GPU1_9) U15.Y34(VDD_GPU1_10) ; also on sheet 6
VCC_LDO_SD1: C51.1 C416.1 R56.1 TP78.1(Pin1) U15.M36(VDD_USDHC1_1P8_3P3_1) U15.N37(VDD_USDHC1_1P8_3P3_2) ; also on sheet 18
VCC_LDO_SD2: C413.1 U15.M38(VDD_USDHC2_1P8_3P3_1) ; also on sheet 6
VCC_LDO_SIM: C352.1 U15.AK42(VDD_SIM0_1P8_3P3) ; also on sheet 2 6
VCC_MAIN: C16.1 C20.1 C273.1 C278.1 C315.1 C316.1 C317.1 C320.1 C321.1 C325.1 C328.1 C338.1 C349.1 C367.1 C369.1 C380.1 C383.1 C390.1 C396.1 C403.1 C554.1 C555.1 L1.1 L3.1 TP8.1(Pin1) U10.2(SW2FB) U10.3(SW1FB) U15.AA23(VDD_MAIN_1) U15.AA27(VDD_MAIN_2) U15.AA31(VDD_MAIN_3) U15.AB24(VDD_MAIN_4) U15.AB28(VDD_MAIN_5) U15.AC25(VDD_MAIN_6) U15.AC29(VDD_MAIN_7) U15.AD26(VDD_MAIN_8) U15.AD30(VDD_MAIN_9) U15.AE23(VDD_MAIN_10) U15.AE27(VDD_MAIN_11) U15.AE31(VDD_MAIN_12) U15.AF20(VDD_MAIN_13) U15.AF24(VDD_MAIN_14) U15.AF28(VDD_MAIN_15) U15.AF32(VDD_MAIN_16) U15.AF36(VDD_MAIN_17) U15.AG21(VDD_MAIN_18) U15.AG33(VDD_MAIN_19) U15.AH18(VDD_MAIN_20) U15.AH34(VDD_MAIN_21) U15.AJ19(VDD_MAIN_22) U15.AJ31(VDD_MAIN_23) U15.AK32(VDD_MAIN_24) U15.AK36(VDD_MAIN_25) U15.AL17(VDD_MAIN_26) U15.AL21(VDD_MAIN_27) U15.AL25(VDD_MAIN_28) U15.AL37(VDD_MAIN_29) U15.AM18(VDD_MAIN_30) U15.AN19(VDD_MAIN_31) U15.AP20(VDD_MAIN_32) U15.AP36(VDD_MAIN_33) U15.AR17(VDD_MAIN_34) U15.AR37(VDD_MAIN_35) U15.AT18(VDD_MAIN_36) U15.AT26(VDD_MAIN_37) U15.AT30(VDD_MAIN_38) U15.AU29(VDD_MIPI_DSI0_1P0) U15.AU35(VDD_MAIN_39) U15.AV26(VDD_MIPI_CSI0_1P0) U15.AV28(VDD_MIPI_DSI1_1P0) U15.AV36(VDD_LVDS0_1P0) U15.AW25(VDD_MIPI_CSI1_1P0) U15.AW27(VDD_MIPI_DSI1_PLL_1P0) U15.AW29(VDD_MIPI_DSI0_PLL_1P0) U15.AW35(VDD_LVDS1_1P0) U15.T34(VDD_MAIN_40) U15.U19(VDD_MAIN_41) U15.U23(VDD_MAIN_42) U15.V24(VDD_MAIN_43) U15.V32(VDD_MAIN_44) U15.W25(VDD_MAIN_45) U15.W29(VDD_MAIN_46) U15.Y26(VDD_MAIN_47) U15.Y30(VDD_MAIN_48)
VCC_MEMC: C357.1 C358.1 C361.1 C363.1 C385.1 C392.1 C427.1 C434.1 C438.1 U15.AC17(VDD_MEMC_1) U15.AC37(VDD_MEMC_2) U15.AG17(VDD_MEMC_3) U15.AG25(VDD_MEMC_4) U15.AG29(VDD_MEMC_5) U15.AG37(VDD_MEMC_6) U15.AH22(VDD_MEMC_7) U15.AH26(VDD_MEMC_8) U15.AH30(VDD_MEMC_9) U15.AJ23(VDD_MEMC_10) U15.AJ27(VDD_MEMC_11) U15.AK24(VDD_MEMC_12) U15.AK28(VDD_MEMC_13) U15.W17(VDD_MEMC_14) U15.W37(VDD_MEMC_15) ; also on sheet 6
VCC_PCIE_1V8: C318.1 C319.1 C322.1 C344.1 C393.1 C399.1 C405.1 C419.1 C424.1 L20.1 L21.1 U15.AL11(VREFH_ADC) U15.AL15(VDD_ADC_1P8) U15.AU23(VDD_MIPI_CSI1_1P8) U15.AV18(VDD_HDMI_RX0_1P8) U15.AV24(VDD_MIPI_CSI0_1P8) U15.AV30(VDD_MIPI_DSI1_1P8) U15.AV34(VDD_LVDS0_1P8) U15.AW17(VDD_HDMI_TX0_1P8) U15.AW31(VDD_MIPI_DSI0_1P8) U15.AW33(VDD_LVDS1_1P8) U15.M22(VDD_PCIE1_PLL_1P8) U15.N21(VDD_PCIE_SATA0_PLL_1P8) U15.N27(VDD_PCIE0_PLL_1P8) U15.T26(VDD_PCIE_IOB_1P8) U15.T30(VDD_MLB_1P8) U15.U27(VDD_PCIE_LDO_1P8) U15.U29(VDD_ANA0_1P8_1) U15.U31(VDD_ANA0_1P8_2) U15.V28(VDD_USB_HSIC0_1P8) ; also on sheet 23 25
VCC_SCU_1V8: C40.1 C272.1 C302.1 C309.1 C343.1 C345.1 C346.1 C350.1 L17.2 R23.1 R24.1 R30.1 R31.2 R53.1 R57.2 R228.1 R244.1 R253.1 R254.2 TP11.1(Pin1) U15.AJ35(VDD_ANA2_1P8) U15.AK20(VDD_ANA3_1P8) U15.AN37(VDD_CP_1P8) U15.AN39(VDD_SCU_1P8_1) U15.AP38(VDD_SCU_1P8_2) U15.AR39(VDD_SCU_ANA_1P8) U15.U25(VDD_ANA1_1P8) U39.5(VCC) ; also on sheet 6 14 19 20 21
VCC_SNVS: C330.1 R227.2 U15.AT38(VDD_SNVS_4P2) ; also on sheet 20
VCC_SNVS_LDO_1V8: C311.1 U15.AW39(VDD_SNVS_LDO_1P8_CAP) ; also on sheet 14
VCCA_PMIC1_1V5: C23.1 R28.2 U10.41(V1P5A)
VCCD_PMIC1_1V5: C32.1 R26.1 R61.1 U10.40(V1P5D)
VDD_HDMI_RX0_LDO0_1P0_CAP: C308.1 C312.1 U15.AU19(VDD_HDMI_RX0_LDO0_1P0_CAP)
VDD_HDMI_RX0_LDO1_1P0_CAP: C310.1 C313.1 U15.AU21(VDD_HDMI_RX0_LDO1_1P0_CAP)
VDD_HDMI_TX0_LDO_1P0_CAP: C306.1 C307.1 U15.AV16(VDD_HDMI_TX0_1P0) U15.AW15(VDD_HDMI_TX0_LDO_1P0_CAP)
VDD_M1P8_CAP: C333.1 U15.AP42(VDD_M1P8_CAP)
VDD_PCIE_LDO_1P0_CAP: C407.1 C417.1 U15.M24(VDD_PCIE_SATA0_1P0) U15.M26(VDD_PCIE0_1P0) U15.N25(VDD_PCIE1_1P0) U15.N29(VDD_PCIE_LDO_1P0_CAP)
VDD_SCU_XTAL_1P8: C300.1 C323.1 L17.1 U15.AU39(VDD_SCU_XTAL_1P8)
VDD_USB_SS3_LDO_1P0_CAP: C408.1 C411.1 C414.1 U15.M30(VDD_USB_SS3_LDO_1P0_CAP) U15.M32(VDD_USB_OTG1_1P0) U15.N31(VDD_USB_OTG2_1P0)
VDDOTP_PMIC1: R25.2 R26.2 U10.53(VDDOTP)
VSS_SCU_XTAL: R237.1 ; also on sheet 13
AMUX_PMIC1: TP7.1(Pin1) U10.52(AMUX)
BB_ENET_DETECT_B: U12.5(S) ; also on sheet 2
LDO_OUT0_5V: C483.1 R336.1 U49.6(S_CTRL) U49.10(VCC/LDO_OUT)
LDO_OUT1_5V: C482.1 R343.1 U50.6(S_CTRL) U50.10(VCC/LDO_OUT)
LDO_OUT2_5V: C490.1 R353.1 R357.2 U52.10(VCC/LDO_OUT)
LX1_CPU1: L5.2 U10.9(SW3LX)
LX1_MAIN: L1.2 U10.5(SW1LX)
LX2_CPU1: L6.2 U10.10(SW4LX)
LX2_MAIN: L3.2 U10.6(SW2LX)
LX_1V8: L2.2 U10.36(SW7LX)
LX_CPU0: L7.2 U10.33(SW5LX)
LX_DDRIO1: L4.2 U10.34(SW6LX)
PG_1V8: R353.2 TP72.1(Pin1) U52.7(PGOOD)
PG_3V3: R343.2 TP62.1(Pin1) U50.7(PGOOD)
PG_5V0: R336.2 TP64.1(Pin1) U49.7(PGOOD)
PMIC1_FSOB: R57.1 U10.29(FSOB)
PMIC1_INT_B: R68.2 R254.1 ; also on sheet 14
PMIC1_LDO3: C42.1 R253.2 TP25.1(Pin1) U10.25(LDO3OUT)
PMIC1_LDO4: C45.1 TP26.1(Pin1) U10.28(LDO4OUT)
PMIC1_PGOOD: R31.1 TP6.1(Pin1) U10.42(PGOOD)
PMIC1_SYNCIN: R27.1 U10.48(SYNCIN)
PMIC2_INT_B: R44.2 ; also on sheet 6
PMIC_EWARN: R64.2 R249.1 ; also on sheet 6 14
PMIC_I2C_SCL: R24.2 U10.55(SCL) ; also on sheet 6 14
PMIC_I2C_SDA: R23.2 U10.56(SDA) ; also on sheet 6 14
PMIC_NC2: R28.1 U10.44(XFAILB) ; also on sheet 6
PMIC_POR_B_1V8: R65.2 U39.2(A) ; also on sheet 6 14 20
PMIC_WDOG_IN: R63.2 ; also on sheet 6 20
PS_GND: C234.2 C548.1 D32.A FL6.3(PSG) J16.1(V+) J16.3(V+) R375.2
SCU_PMIC_ON_REQ: R66.2 ; also on sheet 6 14
SCU_PMIC_STANDBY: R67.2 ; also on sheet 6 14 20
TBBEN_PMIC1: R59.2 R61.2 U10.14(TBBEN)
USDHC1_ENABLE: R29.2 R30.2 U10.43(LDO2EN)
USDHC1_VSELECT: R55.2 R244.2 U10.16(VSELECT) ; also on sheet 18
N1294914: C329.1 C415.1 C435.1 L22.2 U15.AV20(VDD_HDMI_RX0_VH_RX_3P3) U15.M34(VDD_USB_OTG2_3P3) U15.N33(VDD_USB_OTG1_3P3)
N3685764: D34.1(A1) D34.3(A2) F1.2
N3686816: C234.1 D32.C D34.4(C) FL6.1(B)
N3687050: D13.A(ANODE) R166.2
N15185239: D9.A(ANODE) R280.1
N15186263: D10.A(ANODE) R278.1
N15354818: D8.A(ANODE) R316.1
N15495010: D5.A(ANODE) R224.1
N16308260: C300.2 R237.2
N16536163: C22.1 U10.46(LICELL)
N16536317: R65.1 U10.21(~{RESET}_MCU)
N16536490: R64.1 U10.20(EWARN)
N16536673: R44.1 U10.39(XINTB)
N16536839: R67.1 U10.23(STANDBY)
N16536914: R66.1 U10.22(PWRON)
N16537028: R63.1 U10.19(WDI)
N16538232: C21.1 R228.2 U10.54(VDDIO)
N16555069: C277.2 R227.1 U10.47(VSNVS)
N16559570: C41.1 C43.1 C44.1 R246.1 R247.1 U10.17(LDO12IN) U10.26(LDO3IN) U10.27(LDO4IN)
N16670589: R53.2 U10.15(LDO1OUT)
N16670632: R56.2 U10.18(LDO2OUT)
N16913327: R68.1 U10.24(~{INT})
N18421583: F1.1 J16.2(GND1) J16.4(GND2)
N18466055: D5.C(CATHODE) Q3.3(DRAIN)
N18466109: D8.C(CATHODE) Q9.3(DRAIN)
N19116706: C115.2 L23.1 U49.12(SW)
N19116708: C115.1 U49.14(BOOT)
N19116754: C123.2 U49.2(VREF)
N19116787: C487.2 R322.1 R325.2 U49.15(ENABLE)
N19116837: R335.1 U49.5(RT/SYNC)
N19116888: C493.1 R346.2 R354.2 U49.8(VSNS)
N19116928: C495.2 C499.2 U49.3(COMP)
N19116942: C499.1 R332.1
N19116944: C495.1 R330.2 R331.1 R332.2 R334.2 U49.1(FB)
N19117008: C501.1 R330.1 R349.2
N19117016: C501.2 R331.2
N19143019: C121.2 U52.14(BOOT)
N19143032: C121.1 L25.1 U52.12(SW)
N19143038: C502.2 C507.2 U52.3(COMP)
N19143044: C507.1 R363.1
N19143046: C502.1 R352.1 R361.2 R362.2 R363.2 U52.1(FB)
N19143089: C506.1 R360.2 R361.1
N19143100: C506.2 R352.2
N19143303: R347.1 U52.8(LDO_SELECT)
N19143309: R146.2 U52.5(RT/SYNC)
N19143335: R350.1 R357.1 U52.6(SS_SELECT)
N19143378: R329.1 U52.15(ENABLE)
N19165652: C118.2 L24.1 U50.12(SW)
N19165654: C118.1 U50.14(BOOT)
N19165700: C122.2 U50.2(VREF)
N19165733: C491.2 R324.1 R327.2 U50.15(ENABLE)
N19165780: R342.1 U50.5(RT/SYNC)
N19165806: C492.1 R337.2 R351.2 U50.8(VSNS)
N19165827: C496.2 C497.2 U50.3(COMP)
N19165831: C497.1 R340.1
N19165833: C496.1 R338.2 R339.1 R340.2 R341.2 U50.1(FB)
N19165888: C505.1 R338.1 R355.2
N19165896: C505.2 R339.2
N19178714: Q3.1(GATE) U39.4(Y)
N19410380: L8.1 U12.1(Z)
N19872954: H1.1 TP4.1(Pin1)

Not connected (* = marked no-connect by the designer): U10 1(NC1)* 49(SYNCOUT)*; U49 16(VP)*; U50 16(VP)*; U52 2(NC)* 16(SEQ)*

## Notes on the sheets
sheet 10
- POWER SUPPLY
- 12V TO 5V
- Note: Regulator will be enabled
  once the VCC_12V0 is above 9V
- 12V DC INPUT DIN CONNECTOR
- Vout=(0.5*(1+Rf1/Rf2))
- DIN Connector(J16):
- Switching Frequency:600kHz
- Part number: KPJX-4S-S
  Vendor       : Kycon
- 12V TO 3.3V
- FAN CONNECTOR
- Note: Regulator will be enabled
  once the VCC_12V0 is above 9V
- LDO FOR 1V2:VDD_USB_HSIC0_1P2
- Vout=(0.5*(1+Rf1/Rf2))
- Switching Frequency:600kHz
- 12V TO 1.8V
- POWER LEDS
- Note: Regulator will be enabled
  once the VCC_1V8 is UP
- Vout=(0.6*(1+Rf1/Rf2))
- Switching Frequency:600kHz
sheet 11
- POWER SUPPLY - PMIC 1
- IMX8 RESET INDICATION
- LED WILL BE ON WHEN IMX8 IS IN ACTIVE STATE
sheet 12
- Mount devices between dashed green
  lines and U15 symbol under BGA.
- IMX8QM POWER
- Tie this cap to GND.
   Place under IC
- Tie this R+C to VSS_SCU_XTAL.
- See MLB note.
- See MLB note.
- Sourced by
  ENET Card
  when ENET
  daughter card
  plugged in BB
  Pwr net =
  VCC_BB_ENT1IO
- Sourced by
  CPU Card
  (bias only)
  when unused
- Processor does not support MLB.
  VDD_MLB_1P8 may be tied to the power supply voltage shown or
  may be terminated, per the Hardware Developer’s Guide power
  supplies of unused functions.
  VDD_MLB_DIG_1P8_3P3 may be tied to the power supply voltage
  shown if other I/O functions are used, as determined by IOMUX
  selection. Alternately, terminate the MLB supply per the
  Hardware Developer’s Guide power supplies of unused functions.
- Sourced by PHY.
  Software must program
  PHY reg to output 1.8 V.
- 0 = Y0 closed
  1 = Y1 closed
